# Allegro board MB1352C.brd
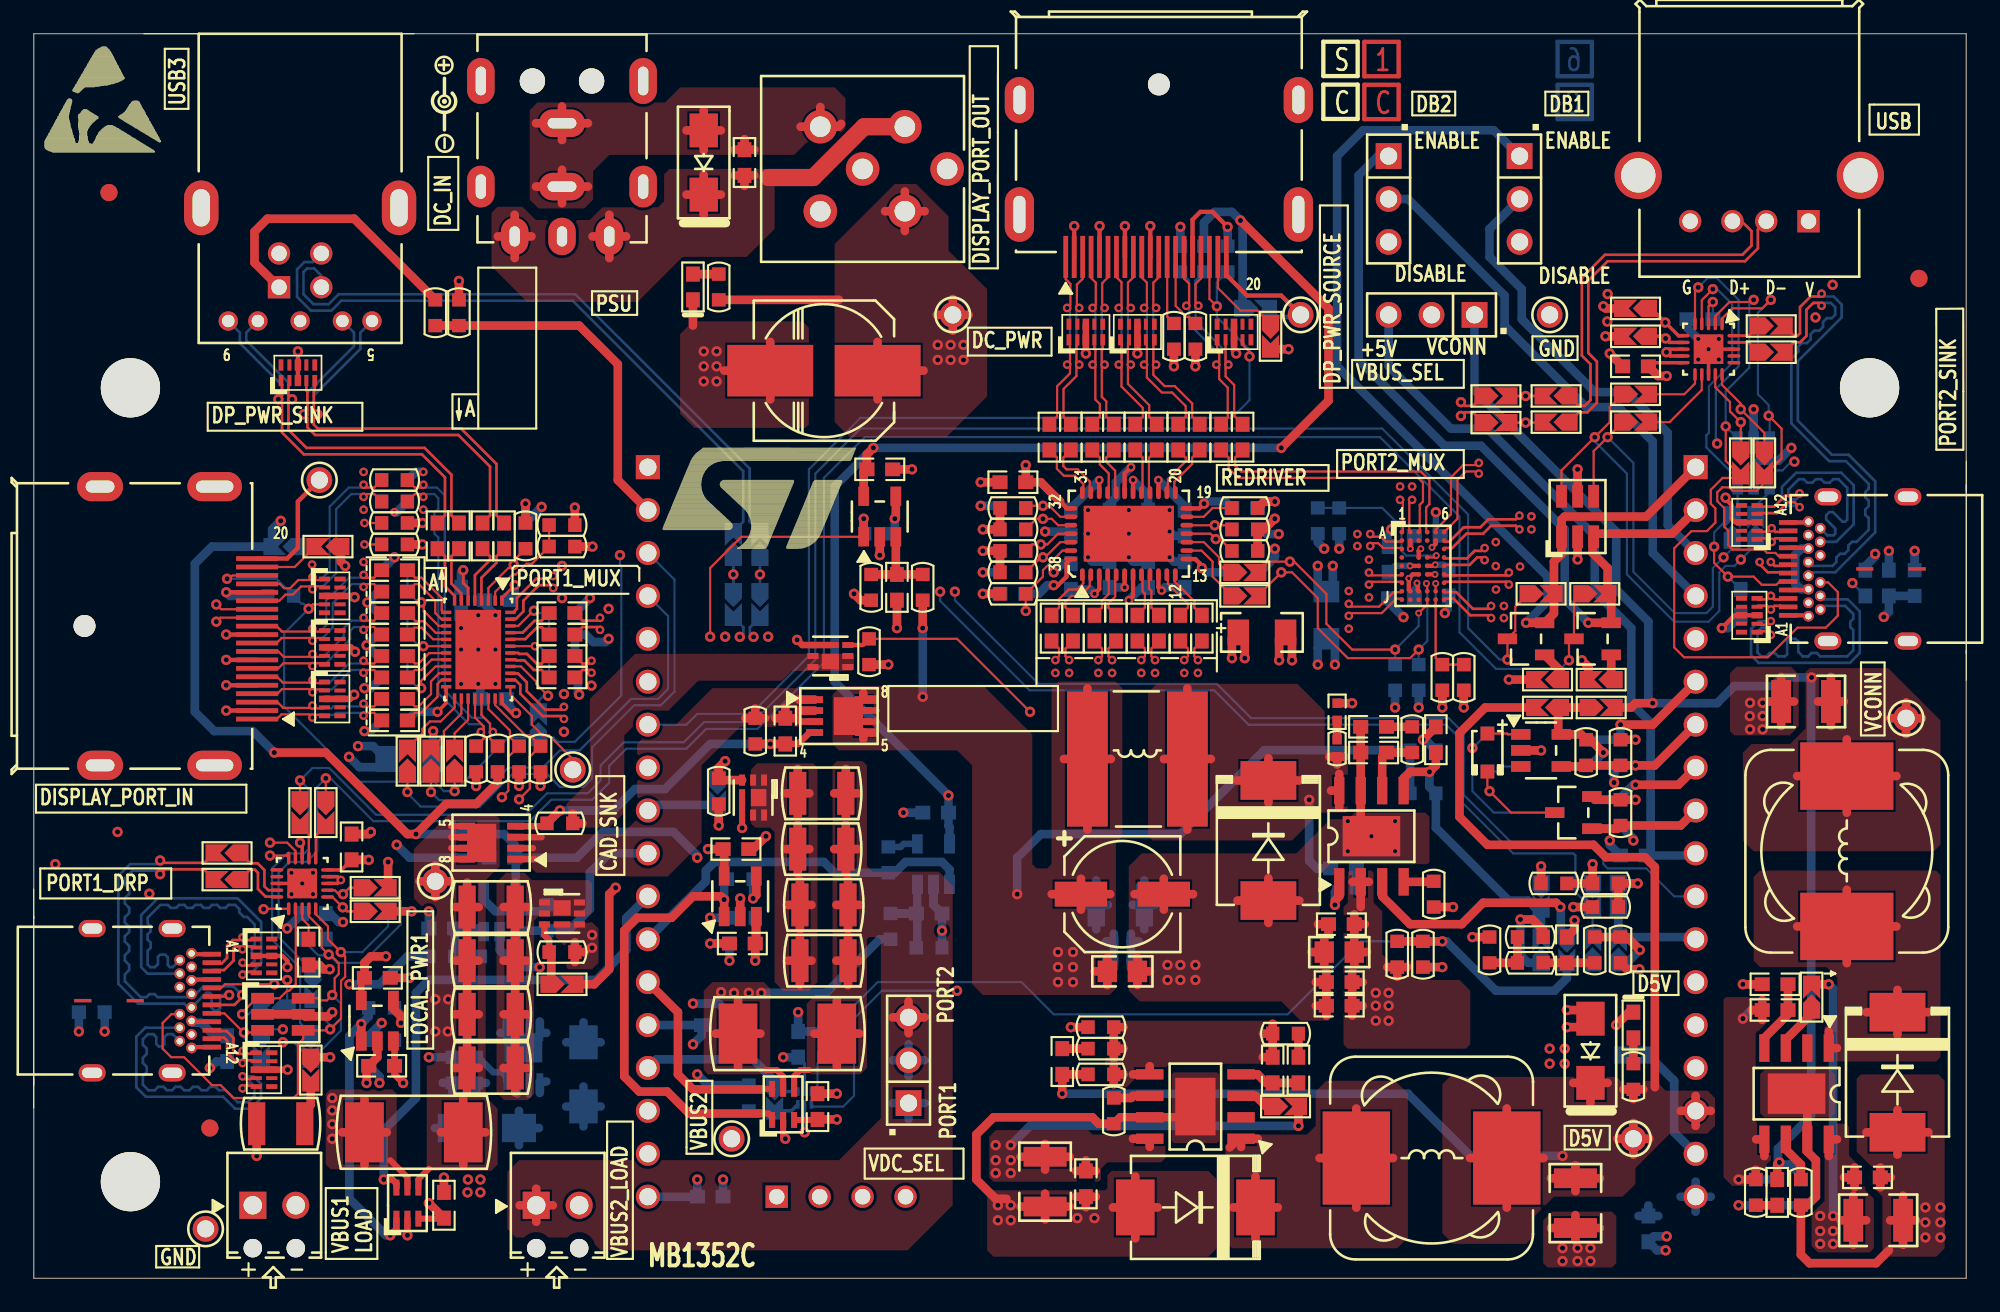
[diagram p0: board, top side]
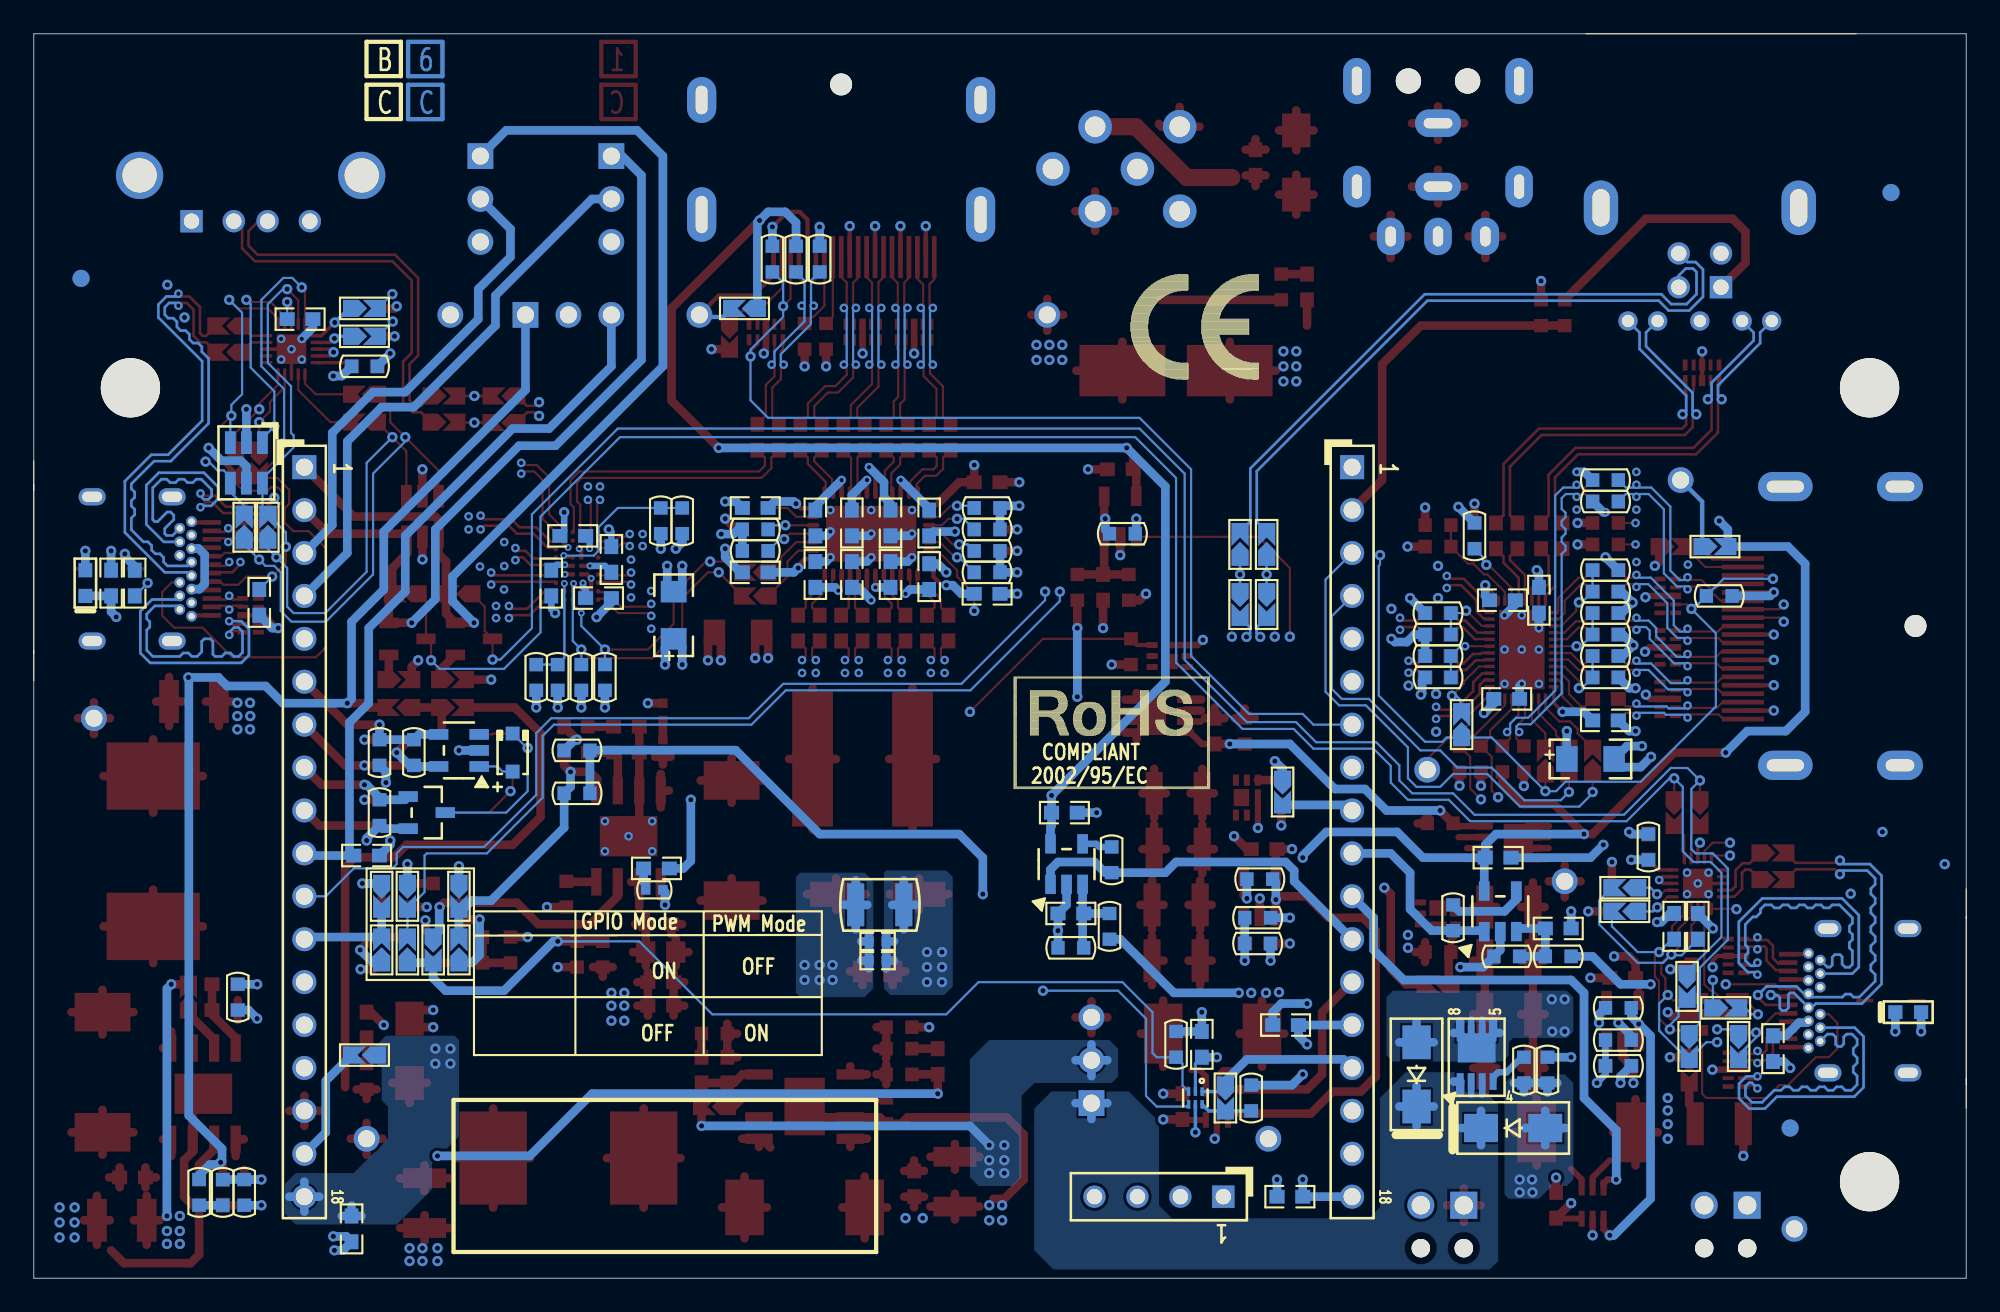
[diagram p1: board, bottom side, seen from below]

Outline 114.3 x 73.66 mm; copper layers: TOP, L2_GND, L3_SIG, L4_VCC, L5_GND, BOTTOM. Coordinates in mm from the lower left corner of the outline.
Outline path: 0,21.28 0,73.66 114.3,73.66 114.3,46.6 ; 0,21.28 0,23.05 ; 0,21.28 0,11.83 ; 0,11.83 0,10.05 ; 0,11.83 0,0 114.3,0 114.3,37.15 ; 114.3,46.6 114.3,48.38 ; 114.3,46.6 114.3,37.16 114.3,37.15 114.3,37.15 ; 114.3,37.15 114.3,35.38

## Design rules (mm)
net group AUX_P: nets AUX_N_2 AUX_P_2
net group AUX_P_1: nets AUX_N_1 AUX_P_1
net group C1_D: nets C1_D+ C1_D-
net group C1_RX1: nets C1_RX1+ C1_RX1-
net group C1_RX2: nets C1_RX2+ C1_RX2-
net group C1_TX1: nets C1_TX1+ C1_TX1-
net group C1_TX2: nets C1_TX2+ C1_TX2-
net group C2_D: nets C2_D+ C2_D-
net group C2_RX1: nets C2_RX1+ C2_RX1-
net group C2_RX2: nets C2_RX2+ C2_RX2-
net group C2_TX1: nets C2_TX1+ C2_TX1-
net group C2_TX2: nets C2_TX2+ C2_TX2-
net group CON1_D: nets CON1_D+ CON1_D-
net group CON2_D: nets CON2_D+ CON2_D-
net group DIFFPAIR18: nets NETCN1_2 NETCN1_3
net group DIFFPAIR20: nets NETC19_2 NETC20_2
net group DIFFPAIR21: nets NETC21_2 NETC22_2
net group DIFFPAIR22: nets NETC26_1 NETC37_1
net group DIFFPAIR23: nets NETC40_1 NETC43_1
net group DIFFPAIR24: nets NETC23_2 NETC24_2
net group DIFFPAIR25: nets NETC25_2 NETC36_2
net group DIFFPAIR26: nets NETC39_2 NETC42_2
net group DIFFPAIR27: nets NETC44_2 NETC46_2
net group DIFFPAIR28: nets NETC27_1 NETC28_1
net group DIFFPAIR29: nets NETC27_2 NETC28_2
net group DIFFPAIR30: nets NETC29_2 NETC30_2
net group DIFFPAIR31: nets NETC29_1 NETC30_1
net group DIFFPAIR32: nets NETC31_2 NETC32_2
net group DIFFPAIR33: nets NETC31_1 NETC32_1
net group DIFFPAIR34: nets NETC33_2 NETC34_2
net group DIFFPAIR35: nets NETC33_1 NETC34_1
net group DIFFPAIR36: nets NETC5_1 NETC6_1
net group DIFFPAIR37: nets NETC7_1 NETC8_1
net group DIFFPAIR38: nets NETC9_1 NETC10_1
net group DIFFPAIR39: nets NETC11_1 NETC12_1
net group DIFFPAIR40: nets NETC13_1 NETC14_1
net group DIFFPAIR41: nets NETR11_1 NETR12_1
net group DIFFPAIR42: nets NETCN4_2 NETCN4_3
net group DIFFPAIR43: nets NETSB70_2 NETSB71_2
net group DIFFPAIR44: nets NETSB68_2 NETSB69_2
net group L0_P: nets L0_N_2 L0_P_2
net group L0_P_1: nets L0_N_1 L0_P_1
net group L1_P: nets L1_N_2 L1_P_2
net group L1_P_1: nets L1_N_1 L1_P_1
net group L2_P: nets L2_N_2 L2_P_2
net group L2_P_1: nets L2_N_1 L2_P_1
net group L3_P: nets L3_N_2 L3_P_2
net group L3_P_1: nets L3_N_1 L3_P_1
net group SSRX: nets SSRX+ SSRX-
net group SSTX: nets SSTX+ SSTX-

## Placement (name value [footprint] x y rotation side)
C1  100nF_50V  [0603C]  42.04 66.04 90 top
C2  220uF_50V  [C310M-6]  46.74 53.72 0 top
C3  22nF  [0603C]  24.13 20.7 180 bottom
C4  220nF[N_A]  [0603C]  44.45 32.38 270 top
C5  100nF  [0603C]  60.07 49.78 90 top
C6  100nF  [0603C]  61.34 49.78 90 top
C7  100nF  [0603C]  62.61 49.78 90 top
C8  100nF  [0603C]  63.88 49.78 90 top
C9  100nF  [0603C]  65.15 49.78 90 top
C10  100nF  [0603C]  66.42 49.78 90 top
C11  100nF  [0603C]  67.69 49.78 90 top
C12  100nF  [0603C]  68.96 49.78 90 top
C13  100nF  [0603C]  70.23 49.78 90 top
C14  100nF  [0603C]  71.5 49.78 90 top
C15  1uF[N_A]  [0603C]  109.73 41.15 270 bottom
C16  1uF[N_A]  [0603C]  11.43 13.59 90 bottom
C17  100nF  [0603C]  57.91 47.12 180 top
C18  22nF  [0603C]  52.96 21.59 0 bottom
C19  100nF  [0603C]  23.88 43.94 270 top
C20  100nF  [0603C]  25.15 43.94 270 top
C21  100nF  [0603C]  26.54 43.94 270 top
C22  100nF  [0603C]  27.81 43.94 270 top
C23  100nF  [0603C]  21.34 41.91 0 top
C24  100nF  [0603C]  21.34 40.64 0 top
C25  100nF  [0603C]  21.34 39.37 0 top
C26  100nF  [0603C]  31.24 39.37 0 top
C27  100nF  [0603C]  60.2 38.48 90 top
C28  100nF  [0603C]  61.47 38.48 90 top
C29  100nF  [0603C]  62.74 38.48 90 top
C30  100nF  [0603C]  64.01 38.48 90 top
C31  100nF  [0603C]  65.28 38.48 90 top
C32  100nF  [0603C]  66.55 38.48 90 top
C33  100nF  [0603C]  67.82 38.48 90 top
C34  100nF  [0603C]  69.09 38.48 90 top
C35  10uF  [TAN-A]  72.64 38.23 180 top
C36  100nF  [0603C]  21.34 38.1 0 top
C37  100nF  [0603C]  31.24 38.1 0 top
C38  100nF  [0603C]  45.21 13.84 90 bottom
C39  100nF  [0603C]  21.34 36.83 0 top
C40  100nF  [0603C]  31.24 36.83 0 top
C41  100nF  [0603C]  50.04 47.88 0 top
C42  100nF  [0603C]  21.34 35.56 0 top
C43  100nF  [0603C]  31.24 35.56 0 top
C44  100nF  [0603C]  21.34 34.29 0 top
C45  47uF_25V  [1210C]  104.83 34.14 180 top
C46  100nF  [0603C]  21.34 33.02 0 top
C47  1uF_X5R_0603  [0603C]  94.74 53.98 0 top
C48  10nF  [0603C]  51.05 40.89 270 top
C49  750pF_50V  [0603C]  79.25 32.64 180 top
C50  11pF_50V  [0603C]  79.25 31.11 180 top
C51  1uF_X5R_0603  [0603C]  18.8 25.53 270 top
C52  22uF[GRM21BR6E226ME44]  [0805C]  64.39 18.16 0 top
C53  56uF_25V[25SVPF56M]  [CAE_6R6X6R6_H5R9]  64.39 22.73 0 top
C54  100nF  [0603C]  16.26 19.3 270 top
C55  39nF_50V  [0603C]  103 17.4 0 top
C56  100nF  [0603C]  77.47 24.26 180 bottom
C57  470nF_50V  [0603C]  90.68 19.43 90 top
C58  680pF_50V  [0603C]  103 15.88 0 top
C59  2.2uF[GRM188R61E225MA12]  [0603C]  77.34 20.95 180 top
C60  7.5nF_50V  [0603C]  60.83 12.83 90 top
C61  2.2nF_50V  [0603C]  73.28 12.32 270 top
C62  39nF_50V  [0603C]  74.8 12.32 270 top
C63  100nF  [0603C]  20.32 17.78 0 top
C64  100nF  [0603C]  41.53 25.4 0 top
C65  220nF_50V  [0603C]  108.46 5.97 0 top
C66  3.3uF_50V  [1210C]  59.82 5.71 270 top
C67  220nF_50V[N_A]  [0603C]  62.23 5.59 270 top
C68  100nF  [0603C]  24.26 4.32 90 top
C69  100nF  [0603C]  46.35 10.16 90 top
C70  33uF(TPS83360160500)  [1210C]  91.19 4.45 270 top
C71  10uF_50V  [1210C]  109.09 3.43 0 top
C72  100nF  [0603C]  20.57 12.57 180 top
C73  100nF  [0603C]  41.91 19.81 180 top
C74  8.2nF_50V  [0603C]  103.12 5.08 270 top
C75  100nF  [0603C]  71.63 45.59 0 bottom
C76  100nF  [0603C]  68.07 44.7 270 bottom
C77  100nF  [0603C]  65.91 44.7 270 bottom
C78  100nF  [0603C]  63.63 44.7 270 bottom
C79  100nF  [0603C]  61.34 44.7 270 bottom
C80  100nF  [0603C]  82.42 43.94 0 bottom
C81  100nF  [0603C]  80.14 42.55 90 bottom
C82  100nF  [0603C]  71.63 41.78 0 bottom
C83  100nF  [0603C]  68.07 41.66 90 bottom
C84  100nF  [0603C]  65.91 41.66 90 bottom
C85  100nF  [0603C]  63.63 41.66 90 bottom
C86  100nF  [0603C]  61.34 41.53 90 bottom
C87  100nF  [0603C]  83.69 41.15 270 bottom
C88  100nF  [0603C]  57.91 40.51 180 bottom
C89  100nF  [0603C]  80.9 40.26 180 bottom
C90  100nF  [0603C]  27.43 40.13 180 bottom
C91  100nF  [0603C]  25.27 40.13 270 bottom
C92  10uF  [TAN-A]  76.45 39.24 270 bottom
C93  100nF  [0603C]  27.18 34.29 180 bottom
C94  100nF  [0603C]  21.34 33.02 180 bottom
C95  10uF  [TAN-A]  22.23 30.73 0 bottom
C96  100nF  [0603C]  98.55 56.77 180 bottom
C97  100nF  [0603C]  94.61 25.02 180 bottom
C98  100nF  [0603C]  53.34 27.56 180 bottom
C99  100nF  [0603C]  27.69 24.89 180 bottom
C100  100nF  [0603C]  40.26 14.99 0 bottom
C101  100nF  [0603C]  40.01 4.83 0 bottom
C102  100nF  [0603C]  95.5 2.92 270 bottom
C103  1uF[GRM155R61E105MA12]  [0402C]  64.39 18.8 0 bottom
C104  4.7nF[GRM155R71E472KA01]  [0402C]  64.39 19.94 0 bottom
C105  22uF[GRM21BR6E226ME44]  [0805C]  77.22 19.3 180 top
C106  2.2uF[GRM188R61E225MA12]  [0603C]  77.22 16.13 180 top
C107  2.2uF[GRM188R61E225MA12]  [0603C]  77.22 17.53 180 top
C108  [N_A]  [0402C]  77.09 33.53 90 top
C109  680pF_50V  [0603C]  82.93 31.88 270 top
C110  390pF[N_A]  [0603C]  100.97 40.01 90 bottom
C111  390pF[N_A]  [0603C]  108.33 41.15 270 bottom
C112  390pF[N_A]  [0603C]  15.88 20.83 270 bottom
C113  390pF[N_A]  [0603C]  17.27 20.83 270 bottom
CN1  319AFKA06CN  [USB_A_4TH]  101.47 65.28 0 top
CN2  Display Port Source(811F20502214)  [HDMI_20SM_4HD_RA]  66.55 60.45 180 top
CN3  DC-094  [PWR_JACK_DC-094]  31.24 70.87 180 top
CN4  31930BFBA07BNHF  [USB_B_9TH_2HD_12X18R3_B]  14.5 58.66 180 top
CN5  317JD24BZTF3K3C3  [USB_C_632723300011]  105.67 41.99 90 top
CN6  Display Port Sink(811F20502214)  [HDMI_20SM_4HD_RA]  13.21 38.61 270 top
CN7  317JD24BZTF3K3C3  [USB_C_632723300011]  8.63 16.43 270 top
CN8  Header 18X1_Female  [SKT_1X18_2R54]  98.3 48.01 270 bottom
CN9  Header 18X1_Female  [SKT_1X18_2R54]  36.32 48.01 270 bottom
CN10  Header 4X1_Female  [SKT_1X4_2R54]  43.94 4.83 0 bottom
CN11  MPT 0.5_2-2.54  [PHOENIX_1725656]  12.95 4.32 0 top
CN12  MPT 0.5_2-2.54  [PHOENIX_1725656]  29.72 4.32 0 top
D1  ESDA25P35-1U1M  [D0603_21]  111.25 41.15 90 bottom
D2  ESDA25SC6[N_A]  [SOT23-6L]  101.73 48.26 0 bottom
D3  STPS2L30A[N_A]  [SMA]  32.51 12.06 90 bottom
D4  B540C-13-F  [SMC]  73.03 25.91 270 top
D5  ESDA25SC6[N_A]  [SOT23-6L]  14.73 15.62 270 top
D6  ESDA25P35-1U1M  [D0603_21]  3.43 15.75 180 bottom
D7  STPS3L40S  [SMC]  110.24 12.19 270 top
D8  STPS2L30A  [SMA]  26.8 8.89 180 bottom
D9  STPS3L40S  [SMC]  68.71 4.19 180 top
D10  ESDA5V3SC6  [SOT23-6L]  91.31 45.09 0 top
D11  BAT60JFILM  [SOD-323]  85.98 31.11 90 bottom
D12  BAT60JFILM  [SOD-323]  85.98 31.11 270 top
JP1  -  [SIP3]  80.14 66.42 270 top
JP2  -  [SIP3]  87.88 66.42 270 top
JP3  -  [SIP3]  85.22 57.02 180 top
JP5  -  [SIP3]  51.74 10.36 90 top
L1  BNX002-01  [BNX001]  49.02 65.66 0 top
L2  4.7uH(SRN8040-4R7Y)  [LSM2_SRN8040]  65.28 30.73 180 top
L4  18uH(MSS1246-183MLB)  [LSM2_12X12_H4R6]  107.24 25.27 90 top
L5  47uH(MSS1246T-473MLB)  [LSM2_12X12_H4R6]  82.68 7.11 0 top
LD1  Green  [0603D]  38.99 58.67 270 top
LD2  Green  [0603D]  94.61 14.99 90 top
NOREF  -  []  384.3 -86.36 0 top
NOREF#2  -  [unnamed#2]  10.41 8.89 0 top
NOREF#3  -  [unnamed#2]  5.71 52.7 0 top
NOREF#4  -  []  79.46 68.86 0 top
NOREF#5  -  []  141.1 158.37 0 top
NOREF#6  -  []  220.14 121.46 0 top
NOREF#7  -  []  5.71 52.7 0 top
NOREF#8  -  []  0 0 0 top
NOREF#9  -  [unnamed#2]  108.58 52.7 0 top
NOREF#10  -  []  5.71 5.71 90 top
NOREF#11  -  []  79.46 71.4 0 top
NOREF#12  -  []  0 73.66 0 top
NOREF#13  -  []  0 0 90 top
NOREF#14  -  [unnamed#2]  5.71 5.71 0 top
NOREF#15  -  [unnamed#2]  4.45 64.26 0 top
NOREF#16  -  []  -3.3 153.54 0 top
NOREF#17  -  [unnamed#2]  111.51 59.18 0 top
NOREF#18  -  []  -7.37 -7.11 0 top
NOREF#19  -  [unnamed#2]  10.41 8.89 180 bottom
NOREF#20  -  [unnamed#2]  4.45 64.26 180 bottom
NOREF#21  -  [unnamed#2]  111.51 59.18 180 bottom
R1  10K  [0603R]  23.75 57.15 270 top
R2  10K  [0603R]  25.15 57.15 90 top
R3  200K[1%]  [0603R]  80.64 19.18 270 top
R4  1M  [0603R]  67.44 55.75 270 top
R5  1M  [0603R]  68.71 55.75 270 top
R6  3K[1%]  [0603R]  82.17 19.18 90 top
R7  0  [0603R]  88.52 20.19 0 top
R8  10K  [0603R]  93.85 31.11 270 top
R9  10K  [0603R]  93.85 31.11 270 bottom
R10  1K  [0603R]  94.61 11.94 270 top
R11  0  [0603R]  21.34 45.97 180 top
R12  0  [0603R]  21.34 47.24 180 top
R13  [N_A]  [0603R]  57.91 45.59 0 top
R14  1.2K  [0603R]  71.63 45.59 0 top
R15  1M  [0603R]  21.34 44.7 180 top
R16  1K  [0603R]  31.24 44.58 0 top
R17  [N_A]  [0603R]  57.91 44.32 0 top
R18  [N_A]  [0603R]  71.63 44.32 0 top
R19  1K  [0603R]  29.08 43.94 90 top
R20  1M  [0603R]  21.34 43.43 180 top
R21  [N_A]  [0603R]  31.24 43.31 180 top
R22  [N_A]  [0603R]  57.91 43.05 0 top
R23  [N_A]  [0603R]  71.63 43.05 0 top
R24  [N_A]  [0603R]  57.91 41.78 0 top
R25  1K[N_A]  [0603R]  57.91 40.51 180 top
R26  1M[N_A]  [0603R]  21.34 45.97 0 bottom
R27  1M[N_A]  [0603R]  21.34 47.24 0 bottom
R28  1K  [0603R]  83.31 35.56 90 top
R29  [N_A]  [0603R]  84.58 35.56 270 top
R30  100K  [0603R]  67.82 60.33 90 bottom
R31  100K  [0603R]  69.22 60.33 90 bottom
R32  330  [0603R]  103.12 5.08 270 bottom
R33  10K[N_A]  [0603R]  91.82 31.11 270 bottom
R34  10K[N_A]  [0603R]  91.82 31.11 90 top
R35  10K  [0603R]  93.85 27.56 90 top
R36  100K  [0603R]  26.16 30.73 90 top
R37  100K  [0603R]  27.43 30.73 90 top
R38  2M  [0603R]  28.7 30.73 90 top
R39  2M  [0603R]  29.97 30.73 90 top
R40  51.1K  [0603R]  81.53 31.88 90 top
R41  2K  [0603R]  31.11 26.92 180 top
R42  21K  [0603R]  42.67 32.38 90 top
R43  12.4K[1%]  [0603R]  89.92 23.37 180 top
R44  9.1K[1%]  [0603R]  92.96 23.37 180 top
R45  220K[1%]  [0603R]  82.17 28.7 180 bottom
R46  20.5K[1%]  [0603R]  92.96 21.97 0 top
R47  1K_0.5W  [1210R]  27.05 15.62 0 top
R48  1K_0.5W  [1210R]  46.74 18.8 180 top
R49  1K_0.5W  [1210R]  27.05 21.97 0 top
R50  1K_0.5W  [1210R]  46.74 22.1 180 top
R51  [N_A]  [0603R]  93.85 19.43 270 top
R52  1K_0.5W  [1210R]  27.05 12.45 0 top
R53  82K[1%]  [0603R]  86.11 19.43 270 top
R54  510[1%]  [0603R]  88.52 18.67 180 top
R55  1K_0.5W  [1210R]  46.61 28.7 180 top
R56  1K_0.5W  [1210R]  27.05 18.8 0 top
R57  49.9K  [0603R]  31.24 19.3 180 top
R58  49.9K  [0603R]  40.51 28.83 90 top
R59  1K_0.5W  [1210R]  46.61 25.4 180 top
R60  [N_A]  [1210R]  64.26 22.1 180 bottom
R61  12K[1%]  [0603R]  92.33 19.43 270 top
R62  93.1K[1%]  [0603R]  82.8 22.73 90 top
R63  330K[1%]  [0603R]  50.67 20.83 270 bottom
R64  330K[1%]  [0603R]  24.13 19.05 180 bottom
R65  680  [0603R]  63.12 14.86 0 top
R66  22K  [0603R]  74.04 14.48 0 top
R67  100  [0603R]  63.12 13.59 180 top
R68  4.99K  [0603R]  63.12 12.06 180 top
R69  0.005[1%]  [2512R]  22.48 8.64 180 top
R70  0.005[1%]  [2512R]  44.58 14.48 180 top
R71  162K  [0603R]  63.88 9.91 90 top
R72  21K  [0603R]  26.16 12.32 90 bottom
R73  21K  [0603R]  24.77 12.32 270 bottom
R74  100  [0603R]  101.85 5.08 270 top
R75  4.99K  [0603R]  104.52 5.08 90 bottom
R76  187K  [0603R]  104.52 5.08 90 top
R77  49.9K[1%]  [0603R]  20.57 14.1 180 bottom
R78  49.9K[1%]  [0603R]  41.91 21.34 180 bottom
R79  49.9K[1%]  [0603R]  20.57 12.57 0 bottom
R80  49.9K[1%]  [0603R]  41.91 19.81 0 bottom
R81  1M  [0603R]  70.61 60.33 90 bottom
R82  [N_A]  [0603R]  46.74 13.84 270 bottom
R83  330K[1%]  [0603R]  52.58 40.89 270 top
R84  49.9K[1%]  [0603R]  49.53 40.89 90 top
R85  1K  [0603R]  57.91 45.59 180 bottom
R86  1K  [0603R]  77.22 44.83 270 bottom
R87  [N_A]  [0603R]  75.95 44.83 90 bottom
R88  1K  [0603R]  71.63 44.32 180 bottom
R89  1K  [0603R]  57.91 44.32 180 bottom
R90  [N_A]  [0603R]  29.08 43.94 270 bottom
R91  1K  [0603R]  71.63 43.05 180 bottom
R92  1K  [0603R]  57.91 43.05 180 bottom
R93  [N_A]  [0603R]  21.34 41.91 0 bottom
R94  [N_A]  [0603R]  57.91 41.78 180 bottom
R95  1K  [0603R]  21.34 40.64 180 bottom
R96  1M  [0603R]  14.61 40.39 180 bottom
R97  [N_A]  [0603R]  31.24 39.37 180 bottom
R98  1K  [0603R]  21.34 39.37 180 bottom
R99  1K  [0603R]  31.24 38.1 0 bottom
R100  [N_A]  [0603R]  21.34 38.1 0 bottom
R101  43K  [0603R]  49.91 44.07 0 bottom
R102  1K  [0603R]  31.24 36.83 0 bottom
R103  1K  [0603R]  21.34 36.83 0 bottom
R104  1K  [0603R]  84.58 35.56 270 bottom
R105  [N_A]  [0603R]  83.31 35.56 90 bottom
R106  10K  [0603R]  81.92 35.56 270 bottom
R107  10K  [0603R]  80.52 35.56 270 bottom
R108  [N_A]  [0603R]  31.24 35.56 180 bottom
R109  [N_A]  [0603R]  21.34 35.56 180 bottom
R110  0  [0402R]  77.6 22.99 180 bottom
R111  [N_A]  [0402R]  77.09 31.37 270 top
R112  100K  [0603R]  94.74 53.98 180 bottom
R113  10K  [0603R]  93.85 27.56 270 bottom
R114  100K  [0603R]  18.8 25.53 90 bottom
R115  43K  [0603R]  50.55 24.77 90 bottom
R116  43K  [0603R]  30.35 21.34 90 bottom
R117  1.2K  [0603R]  102.23 16.64 90 bottom
R118  49.9K[1%]  [0603R]  52.96 19.56 180 bottom
R119  49.9K[1%]  [0603R]  27.18 19.05 180 bottom
R120  15K[1%]  [0603R]  42.29 10.67 90 bottom
R121  24.9K  [0603R]  41.78 23.62 0 bottom
R122  24.9K  [0603R]  20.57 16 0 bottom
R123  680  [0603R]  101.85 5.08 90 bottom
R124  10K  [0603R]  49.4 37.08 90 top
R125  3K  [0603R]  40.51 58.67 270 top
R126  1K_0.5W  [1210R]  14.61 9.14 180 top
R127  0  [0603R]  82.17 31.24 180 bottom
SB1  Solder Bridge ON  [SB_0603]  73.15 55.75 90 top
SB2  Solder Bridge OFF  [SB_0603]  93.73 19.43 270 bottom
SB3  Solder Bridge OFF  [SB_0603]  89.15 19.43 270 bottom
SB4  Solder Bridge OFF  [SB_0603]  89.15 40.51 180 top
SB5  Solder Bridge OFF  [SB_0603]  92.33 40.51 180 top
SB6  Solder Bridge ON  [SB_0603]  17.4 43.31 0 top
SB7  Solder Bridge ON  [SB_0603]  71.63 41.78 180 top
SB8  Solder Bridge OFF  [SB_0603]  89.53 33.78 0 top
SB9  Solder Bridge ON  [SB_0603]  92.71 33.78 180 top
SB10  Solder Bridge ON  [SB_0603]  71.63 40.39 180 top
SB11  Solder Bridge ON  [SB_0603]  92.71 35.43 0 top
SB12  Solder Bridge ON  [SB_0603]  89.53 35.43 0 top
SB13  Solder Bridge ON  [SB_0603]  89.15 22.61 90 bottom
SB14  Solder Bridge ON  [SB_0603]  93.73 22.61 90 bottom
SB15  Solder Bridge ON  [SB_0603]  92.2 22.61 90 bottom
SB16  Solder Bridge OFF  [SB_0603]  94.74 55.75 0 top
SB17  Solder Bridge OFF  [SB_0603]  94.74 57.4 0 top
SB18  Solder Bridge ON  [SB_0603]  22.1 30.61 270 top
SB19  Solder Bridge ON  [SB_0603]  23.5 30.61 270 top
SB20  Solder Bridge ON  [SB_0603]  24.89 30.61 270 top
SB21  Solder Bridge ON  [SB_0603]  15.75 27.56 90 top
SB22  Solder Bridge ON  [SB_0603]  17.27 27.56 90 top
SB23  Solder Bridge OFF  [SB_0603]  92.2 19.43 270 bottom
SB24  Solder Bridge OFF  [SB_0603]  43.81 10.67 90 bottom
SB25  Solder Bridge OFF  [SB_0603]  16.38 12.32 90 top
SB26  Solder Bridge OFF  [SB_0603]  90.68 19.43 90 bottom
SB27  Solder Bridge OFF  [SB_0603]  20.19 21.72 180 top
SB28  Solder Bridge OFF  [SB_0603]  20.19 23.11 180 top
SB33  Solder Bridge ON  [SB_0603]  105.16 16.64 270 top
SB35  Solder Bridge ON  [SB_0603]  31.24 17.4 180 top
SB36  Solder Bridge ON  [SB_0603]  40.44 28.78 90 bottom
SB37  Solder Bridge ON  [SB_0603]  74.04 10.16 180 top
SB40  Solder Bridge ON  [SB_0603]  72.26 57.4 180 bottom
SB41  Solder Bridge OFF  [SB_0603]  102.36 48.26 90 top
SB42  Solder Bridge OFF  [SB_0603]  100.97 48.26 90 top
SB43  Solder Bridge ON  [SB_0603]  14.86 43.31 0 bottom
SB44  Solder Bridge OFF  [SB_0603]  100.46 44.45 270 bottom
SB45  Solder Bridge OFF  [SB_0603]  101.85 44.45 270 bottom
SB48  Solder Bridge OFF  [SB_0603]  29.84 32.77 270 bottom
SB49  Solder Bridge ON  [SB_0603]  94.74 57.4 0 bottom
SB50  Solder Bridge ON  [SB_0603]  94.74 55.75 0 bottom
SB51  Solder Bridge ON  [SB_0603]  94.74 52.32 180 top
SB52  Solder Bridge ON  [SB_0603]  94.74 50.67 180 top
SB53  Solder Bridge OFF  [SB_0603]  14.22 16 0 bottom
SB54  Solder Bridge ON  [SB_0603]  20.19 23.11 180 bottom
SB55  Solder Bridge ON  [SB_0603]  20.19 21.72 180 bottom
SB56  Solder Bridge OFF  [SB_0603]  16.38 13.72 90 bottom
SB57  Solder Bridge OFF  [SB_0603]  16.51 17.27 90 bottom
SB58  Solder Bridge OFF  [SB_0603]  13.46 13.72 90 bottom
SB59  Solder Bridge ON  [SB_0603]  94.74 13.21 180 bottom
SB60  Solder Bridge OFF  [SB_0603]  42.95 39.88 90 bottom
SB61  Solder Bridge OFF  [SB_0603]  41.38 39.88 90 bottom
SB62  Solder Bridge ON  [SB_0603]  42.95 43.43 270 bottom
SB63  Solder Bridge ON  [SB_0603]  41.38 43.43 270 bottom
SB64  Solder Bridge ON  [SB_0603]  90.04 50.67 0 top
SB65  Solder Bridge ON  [SB_0603]  90.04 52.22 0 top
SB66  Solder Bridge OFF  [SB_0603]  86.49 50.65 180 top
SB67  Solder Bridge OFF  [SB_0603]  86.49 52.22 180 top
SB68  Solder Bridge ON  [SB_0603]  102.77 56.36 180 top
SB69  Solder Bridge ON  [SB_0603]  102.77 54.81 180 top
SB70  Solder Bridge ON  [SB_0603]  11.43 23.6 0 top
SB71  Solder Bridge ON  [SB_0603]  11.43 25.17 0 top
T2  FDV303N  [SOT-23]  88.27 37.85 0 top
T3  FDV303N  [SOT-23]  92.2 37.85 0 top
T4  FDV303N  [SOT-23]  91.06 27.56 0 top
T5  STL6N2VH5  [DFN6_0R65_2X2_2TP_C]  47.12 36.83 90 top
T6  STL9P3LLH6  [SOIC8_MOS_S]  27.05 25.78 90 top
T7  STL9P3LLH6  [SOIC8_MOS_S]  47.62 33.27 270 top
T8  STL6N2VH5  [DFN6_0R65_2X2_2TP_C]  31.24 21.59 270 top
T9  STL6N2VH5  [DFN6_0R65_2X2_2TP_C]  42.55 28.45 180 top
T10  STL9P3LLH6  [SOIC8_MOS_S]  28.96 13.08 180 bottom
T12  FDV303N  [SOT-23]  91.06 27.56 0 bottom
TP1  DP_PWR_SOURCE  [TP]  74.93 57.02 180 top
TP2  PSU  [TP]  54.36 57.02 270 top
TP3  Ground  [TP]  89.66 57.02 0 top
TP4  DP_PWR_SINK  [TP]  16.89 47.24 270 top
TP5  VCONN  [TP]  110.74 33.15 90 top
TP6  CAD_SNK  [TP]  31.88 30.1 0 top
TP7  D5V  [TP]  94.61 8.26 90 top
TP8  Ground  [TP]  10.16 2.92 0 top
TP9  LOCAL_PWR1  [TP]  23.75 23.5 0 top
TP10  VBUS2  [TP]  41.27 8.26 0 top
U1  HSP051-4M10  [DFN10_0R5_2R5X1]  62.23 56.01 0 top
U2  HSP051-4M10  [DFN10_0R5_2R5X1]  65.28 56.01 0 top
U3  HSP051-4M10  [DFN10_0R5_2R5X1]  70.99 56.01 0 top
U4  HSP051-4M10  [DFN10_0R5_2R5X1]  15.62 53.59 0 top
U5  HSP051-4M10  [DFN10_0R5_2R5X1]  101.47 44.74 90 top
U6  SN65DP141RLJ  [QFN38_0R5_5X7]  64.77 44.07 90 top
U7  STG5123  [DFN6_0R4_1R2X1]  45.59 10.67 0 bottom
U8  CBTL08GP053EVY  [FBGA40_0R5_3R25X4R75]  82.17 42.16 0 top
U9  HSP051-4M10  [DFN10_0R5_2R5X1]  17.65 40.39 270 top
U10  STMPS2161STR  [SOT23-5]  89.15 31.24 90 bottom
U11  HSP051-4M10  [DFN10_0R5_2R5X1]  101.47 39.24 90 top
U12  HSP051-4M10  [DFN10_0R5_2R5X1]  17.65 37.34 270 top
U13  TUSB546-DCI  [QFN40_0R4_6X4]  26.29 37.21 270 top
U14  STMPS2161STR  [SOT23-5]  89.15 31.24 270 top
U15  HSP051-4M10  [DFN10_0R5_2R5X1]  17.65 34.29 270 top
U16  TPD8S300RUKR  [QFN20_0R4_3X3_TP1R75]  99.06 54.99 270 top
U17  TPD8S300RUKR  [QFN20_0R4_3X3_TP1R75]  15.88 23.37 90 top
U18  TPS54540  [SOIC8_1R27_4R9X6_TP]  79.12 26.16 0 top
U19  HSP051-4M10  [DFN10_0R5_2R5X1]  13.61 19.08 270 top
U20  HSP051-4M10  [DFN10_0R5_2R5X1]  13.61 12.34 270 top
U21  L7985A  [SOIC8_1R27_4R9X6_TP]  104.27 10.92 180 top
U22  L7985A  [SOIC8_1R27_4R9X6_TP]  68.71 10.16 90 top
U23  INA199A1DCKR  [SC70-6]  22.1 4.45 0 top
U24  INA199A1DCKR  [SC70-6]  44.32 10.29 0 top
U25  TSV911ILT  [SOT23-5]  20.32 15.24 0 top
U26  TSV911ILT  [SOT23-5]  41.78 22.61 0 top
U27  TSV911ILT  [SOT23-5]  53.21 24.51 180 bottom
U28  TSV911ILT  [SOT23-5]  27.56 21.72 180 bottom
U29  TSV911ILT  [SOT23-5]  50.04 45.09 0 top
Z1  SMAJ20A-TR  [SMA]  39.62 66.04 90 top
Z2  SMAJ5.0A-TR  [SMA]  92.08 13.46 90 top

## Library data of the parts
C1 C3-C34 C36-C44 C46-C51 C54-C65 C67-C69 C72-C91 C93 C94 C96-C102 C106 C107 C109-C113 = 0603C
C2 = C310M-6
C35 C92 C95 = TAN-A
C45 C66 C70 C71 = 1210C
C52 C105 = 0805C
C53 = CAE_6R6X6R6_H5R9
C103 C104 C108 = 0402C
CN1 = USB_A_4TH
CN2 CN6 = HDMI_20SM_4HD_RA
CN3 = PWR_JACK_DC-094
CN4 = USB_B_9TH_2HD_12X18R3_B
CN5 CN7 = USB_C_632723300011
CN8 CN9 = SKT_1X18_2R54
CN10 = SKT_1X4_2R54
CN11 CN12 = PHOENIX_1725656
D1 D6 = D0603_21
D2 D5 D10 = SOT23-6L
D3 D8 Z1 Z2 = SMA
D4 D7 D9 = SMC
D11 D12 = SOD-323
JP1-JP3 JP5 = SIP3
L1 = BNX001
L2 = LSM2_SRN8040
L4 L5 = LSM2_12X12_H4R6
LD1 LD2 = 0603D
R1-R46 R51 R53 R54 R57 R58 R61-R68 R71-R109 R112-R125 R127 = 0603R
R47-R50 R52 R55 R56 R59 R60 R126 = 1210R
R69 R70 = 2512R
R110 R111 = 0402R
SB1-SB28 SB33 SB35-SB37 SB40-SB45 SB48-SB71 = SB_0603
T2-T4 T12 = SOT-23
T5 T8 T9 = DFN6_0R65_2X2_2TP_C
T6 T7 T10 = SOIC8_MOS_S
TP1-TP10 = TP
U1-U5 U9 U11 U12 U15 U19 U20 = DFN10_0R5_2R5X1
U6 = QFN38_0R5_5X7
U7 = DFN6_0R4_1R2X1
U8 = FBGA40_0R5_3R25X4R75
U10 U14 U25-U29 = SOT23-5
U13 = QFN40_0R4_6X4
U16 U17 = QFN20_0R4_3X3_TP1R75
U18 U21 U22 = SOIC8_1R27_4R9X6_TP
U23 U24 = SC70-6

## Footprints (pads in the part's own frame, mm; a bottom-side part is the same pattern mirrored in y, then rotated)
0402C
  rect 0.559x0.559 smd: 1(-0.508,0) 2(0.508,0)
0402R
  rect 0.559x0.559 smd: 1(-0.508,0) 2(0.508,0)
0603C
  rect 0.889x0.813 smd: 1(-0.762,0) 2(0.762,0)
0603D
  rect 0.889x0.813 smd: 1(-0.762,0) 2(0.762,0)
0603R
  rect 0.787x0.813 smd: 1(-0.762,0) 2(0.762,0)
0805C
  rect 1.143x1.27 smd: 1(-0.889,0) 2(0.889,0)
1210C
  rect 1.168x2.54 smd: 1(-1.473,0) 2(1.473,0)
1210R
  rect 1.016x2.54 smd: 1(-1.422,0) 2(1.422,0)
2512R
  rect 2.286x3.556 smd: 1(-2.921,0) 2(2.921,0)
BNX001
  round 1.981 hole 1.219: 1(2.5,2.5) 2(-2.5,2.5) 3(2.5,-2.5) 4(0,0) 5(5,0) 6(-2.5,-2.5)
C310M-6
  rect 5.08x3.048 smd: 1(3.175,0) 2(-3.175,0)
CAE_6R6X6R6_H5R9
  rect 3.099x1.473 smd: 1(-2.45,0) 2(2.45,0)
D0603_21
  rect 0.838x0.813 smd: 1(-0.762,0) 2(0.762,0)
DFN6_0R4_1R2X1
  rect 0.203x0.508 smd: 1(-0.4,-0.379) 2(0,-0.379) 3(0.4,-0.379) 4(0.4,0.379) 5(0,0.379) 6(-0.4,0.379)
DFN6_0R65_2X2_2TP_C
  rect 0.356x0.66 smd: 1(-0.65,-1.035) 2(0,-1.035) 3(0.65,-1.035) 4(0.65,1.035) 5(0,1.035) 6(-0.65,1.035)
  rect 0.914x1.016 smd: 7(-0.325,0)
  rect 0.356x0.991 smd: 8(0.65,0)
DFN10_0R5_2R5X1
  rect 0.279x0.66 smd: 1(-1,-0.46) 5(1,-0.46) 6(1,0.46) 10(-1,0.46)
  rect 0.229x0.66 smd: 2(-0.5,-0.46) 4(0.5,-0.46) 7(0.5,0.46) 9(-0.5,0.46)
  rect 0.381x0.66 smd: 3(0,-0.46) 8(0,0.46)
FBGA40_0R5_3R25X4R75
  round 0.279 smd: A1(-1.25,2) A2(-0.75,2) A3(-0.25,2) A4(0.25,2) A5(0.75,2) A6(1.25,2) B1(-1.25,1.5) B2(-0.75,1.5) B3(-0.25,1.5) B4(0.25,1.5) B5(0.75,1.5) B6(1.25,1.5) C1(-1.25,1) C6(1.25,1) D1(-1.25,0.5) D3(-0.25,0.5) D4(0.25,0.5) D6(1.25,0.5) E1(-1.25,0) E3(-0.25,0) E4(0.25,0) E6(1.25,0) F1(-1.25,-0.5) F3(-0.25,-0.5) F4(0.25,-0.5) F6(1.25,-0.5) G1(-1.25,-1) G6(1.25,-1) H1(-1.25,-1.5) H2(-0.75,-1.5) H3(-0.25,-1.5) H4(0.25,-1.5) H5(0.75,-1.5) H6(1.25,-1.5) J1(-1.25,-2) J2(-0.75,-2) J3(-0.25,-2) J4(0.25,-2) J5(0.75,-2) J6(1.25,-2)
HDMI_20SM_4HD_RA
  round 1.295 hole 1.295: (0,-10.21)
  rect 0.279x2.489 smd: 1(5.51,0) 2(5.01,0) 3(4.51,0) 4(4.01,0) 5(3.51,0) 6(3.01,0) 7(2.51,0) 8(2.01,0) 9(1.51,0) 10(1.01,0) 11(0.51,0) 12(0.01,0) 13(-0.49,0) 14(-0.99,0) 15(-1.49,0) 16(-1.99,0) 17(-2.49,0) 18(-2.99,0) 19(-3.49,0) 20(-3.99,0)
  oval 1.727x3.226 hole 0.711x2.21: 21(8.25,-2.51) 22(-8.25,-2.51)
  oval 1.727x2.718 hole 0.711x1.702: 23(8.25,-9.29) 24(-8.25,-9.29)
LSM2_12X12_H4R6
  rect 3.988x5.512 smd: 1(-4.45,0) 2(4.45,0)
LSM2_SRN8040
  rect 2.413x8.001 smd: 1(-2.957,0) 2(2.957,0)
PHOENIX_1725656
  round 1.092 hole 1.092 unplated: (0,-2.54) (2.54,-2.54)
  rect 1.6x1.6 hole 1.092: 1(0,0)
  round 1.6 hole 1.092: 2(2.54,0)
PWR_JACK_DC-094
  round 1.499 hole 1.499 unplated: (-1.75,0) (1.75,0)
  oval 2.718x1.626 hole 1.702x0.61: 1(0,6.25) 3(0,2.5)
  oval 1.626x2.21 hole 0.61x1.194: 2(-2.8,9.2) 4(0,9.2) 5(2.8,9.2)
  oval 1.626x2.464 hole 0.61x1.448: 6(-4.8,6.25) 7(4.8,6.25)
  oval 1.626x2.718 hole 0.61x1.702: 8(4.8,0) 9(-4.8,0)
QFN20_0R4_3X3_TP1R75
  oval 0.762x0.203 smd: 1(-1.5,0.8) 2(-1.5,0.4) 3(-1.5,0) 4(-1.5,-0.4) 5(-1.5,-0.8) 11(1.5,-0.8) 12(1.5,-0.4) 13(1.5,0) 14(1.5,0.4) 15(1.5,0.8)
  oval 0.203x0.762 smd: 6(-0.8,-1.5) 7(-0.4,-1.5) 8(0,-1.5) 9(0.4,-1.5) 10(0.8,-1.5) 16(0.8,1.5) 17(0.4,1.5) 18(0,1.5) 19(-0.4,1.5) 20(-0.8,1.5)
  rect 1.753x1.753 smd: 21(0,0)
QFN38_0R5_5X7
  oval 0.762x0.279 smd: 1(-2.431,2.75) 2(-2.431,2.25) 3(-2.431,1.75) 4(-2.431,1.25) 5(-2.431,0.75) 6(-2.431,0.25) 7(-2.431,-0.25) 8(-2.431,-0.75) 9(-2.431,-1.25) 10(-2.431,-1.75) 11(-2.431,-2.25) 12(-2.431,-2.75) 20(2.431,-2.75) 21(2.431,-2.25) 22(2.431,-1.75) 23(2.431,-1.25) 24(2.431,-0.75) 25(2.431,-0.25) 26(2.431,0.25) 27(2.431,0.75) 28(2.431,1.25) 29(2.431,1.75) 30(2.431,2.25) 31(2.431,2.75)
  oval 0.279x0.762 smd: 13(-1.5,-3.435) 14(-1,-3.435) 15(-0.5,-3.435) 16(0,-3.435) 17(0.5,-3.435) 18(1,-3.435) 19(1.5,-3.435) 32(1.5,3.435) 33(1,3.435) 34(0.5,3.435) 35(0,3.435) 36(-0.5,3.435) 37(-1,3.435) 38(-1.5,3.435)
  rect 3.302x5.334 smd: 39(0,0)
QFN40_0R4_6X4
  rect 0.61x0.203 smd: 1(-2.9,1.4) 2(-2.9,1) 3(-2.9,0.6) 4(-2.9,0.2) 5(-2.9,-0.2) 6(-2.9,-0.6) 7(-2.9,-1) 8(-2.9,-1.4) 21(2.9,-1.4) 22(2.9,-1) 23(2.9,-0.6) 24(2.9,-0.2) 25(2.9,0.2) 26(2.9,0.6) 27(2.9,1) 28(2.9,1.4)
  rect 0.203x0.61 smd: 9(-2.2,-1.9) 10(-1.8,-1.9) 11(-1.4,-1.9) 12(-1,-1.9) 13(-0.6,-1.9) 14(-0.2,-1.9) 15(0.2,-1.9) 16(0.6,-1.9) 17(1,-1.9) 18(1.4,-1.9) 19(1.8,-1.9) 20(2.2,-1.9) 29(2.2,1.9) 30(1.8,1.9) 31(1.4,1.9) 32(1,1.9) 33(0.6,1.9) 34(0.2,1.9) 35(-0.2,1.9) 36(-0.6,1.9) 37(-1,1.9) 38(-1.4,1.9) 39(-1.8,1.9) 40(-2.2,1.9)
  rect 4.699x2.692 smd: 41(0,0)
SB_0603
  round 0.152 smd: 1(-0.762,0) 2(0.762,0)
SC70-6
  rect 0.356x0.94 smd: 1(-0.65,-0.92) 2(0,-0.92) 3(0.65,-0.92) 4(0.65,0.92) 5(0,0.92) 6(-0.65,0.92)
SIP3
  rect 1.524x1.524 hole 1.016: 1(0,0)
  round 1.524 hole 1.016: 2(2.54,0) 3(5.08,0)
SKT_1X4_2R54
  rect 1.321x1.321 hole 0.914: 1(0,0)
  round 1.321 hole 0.914: 2(2.54,0) 3(5.08,0) 4(7.62,0)
SKT_1X18_2R54
  rect 1.422x1.422 hole 1.016: 1(0,0)
  round 1.422 hole 1.016: 2(2.54,0) 3(5.08,0) 4(7.62,0) 5(10.16,0) 6(12.7,0) 7(15.24,0) 8(17.78,0) 9(20.32,0) 10(22.86,0) 11(25.4,0) 12(27.94,0) 13(30.48,0) 14(33.02,0) 15(35.56,0) 16(38.1,0) 17(40.64,0) 18(43.18,0)
SMA
  rect 2.007x1.676 smd: 1(1.9,0) 2(-1.9,0)
SMC
  rect 2.286x3.302 smd: 1(3.555,0) 2(-3.555,0)
SOD-323
  rect 0.813x0.813 smd: 1(-1.125,0) 2(1.125,0)
SOIC8_1R27_4R9X6_TP
  rect 0.61x1.626 smd: 1(-1.905,-2.7) 2(-0.635,-2.7) 3(0.635,-2.7) 4(1.905,-2.7) 5(1.905,2.7) 6(0.635,2.7) 7(-0.635,2.7) 8(-1.905,2.7)
  rect 3.404x2.388 smd: 9(0,0)
SOIC8_MOS_S
  rect 0.406x0.991 smd: 1(-0.975,-1.44) 2(-0.325,-1.44) 3(0.325,-1.44) 4(0.975,-1.44) 5(0.975,1.44) 6(0.325,1.44) 7(-0.325,1.44) 8(-0.975,1.44)
SOT23-5
  rect 0.635x1.143 smd: 1(-0.95,-1.2) 2(0,-1.2) 3(0.95,-1.2) 4(0.95,1.2) 5(-0.95,1.2)
SOT23-6L
  rect 0.635x1.346 smd: 1(-0.95,-1.2) 2(0,-1.2) 3(0.95,-1.2) 4(0.95,1.2) 5(0,1.2) 6(-0.95,1.2)
SOT-23
  rect 1.143x0.635 smd: 1(1.1,-0.95) 2(1.1,0.95) 3(-1.1,0)
TAN-A
  rect 1.27x1.524 smd: 1(1.397,0) 2(-1.397,0)
TP
  round 1.524 hole 1.016: 1(0,0)
unnamed#2
  round 1.016 smd: (0,0)
USB_A_4TH
  rect 1.321x1.321 hole 0.914: 1(3.5,-2.71)
  round 1.321 hole 0.914: 2(1,-2.71) 3(-1,-2.71) 4(-3.5,-2.71)
  round 2.794 hole 2.032: 5(-6.57,0) 6(6.57,0)
USB_B_9TH_2HD_12X18R3_B
  rect 1.321x1.321 hole 0.914: 1(0,0)
  round 1.321 hole 0.914: 2(-2.5,0) 3(-2.5,-2) 4(0,-2)
  round 1.143 hole 0.737: 5(-5.5,2) 6(-3.75,2) 7(-1.25,2) 8(1.25,2) 9(3,2)
  oval 2.032x3.226 hole 1.016x2.21: 10(-7.1,-4.7) 11(4.6,-4.7)
USB_C_632723300011
  oval 1.016x1.6 hole 0.61x1.194: 1(-4.27,-0.45) 2(4.27,-0.45) 3(-4.27,-5.18) 4(4.27,-5.18)
  rect 0.203x1.016 smd: 5(0,-2.63) 6(0,-5.73)
  rect 0.279x1.092 smd: A1(-2.75,1.9) A2(-2.25,1.9) A3(-1.75,1.9) A4(-1.25,1.9) A5(-0.75,1.9) A6(-0.25,1.9) A7(0.25,1.9) A8(0.75,1.9) A9(1.25,1.9) A10(1.75,1.9) A11(2.25,1.9) A12(2.75,1.9)
  round 0.635 hole 0.381: B1(2.8,0.7) B2(2.4,0) B3(1.6,0) B4(1.2,0.7) B5(0.8,0) B6(0.4,0.7) B7(-0.4,0.7) B8(-0.8,0) B9(-1.2,0.7) B10(-1.6,0) B11(-2.4,0) B12(-2.8,0.7) B13(2,0.7) B14(-2,0.7)

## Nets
+3V3: C38.1 C41.1 C63.1 C64.1 C68.1 C69.1 C98.1 C99.1 C100.1 CN9.14 R26.2 R31.2 R37.1 R77.2 R78.2 R120.2 SB40.2 SB43.1 U7.2 U23.3 U24.3 U25.5 U26.5 U27.5 U28.5 U29.5
+5V: C97.1 CN8.10 JP3.3
D5V: C60.1 C70.1 CN8.16 L5.2 R10.2 R68.2 SB8.1 TP7.1 Z2.2
GND: C2.2 C3.2 C15.1 C16.1 C17.2 C18.2 C35.2 C38.2 C41.2 C45.2 C47.1 C48.2 C49.2 C50.2 C51.1 C52.2 C53.2 C54.2 C57.2 C59.2 C63.2 C64.2 C65.2 C66.2 C67.2 C68.2 C69.2 C70.2 C71.2 C72.2 C73.2 C75.2 C76.2 C77.2 C78.2 C79.2 C80.2 C81.2 C82.2 C83.2 C84.2 C85.2 C86.2 C87.2 C88.2 C89.2 C90.2 C91.2 C92.2 C93.2 C94.2 C95.2 C96.2 C97.2 C98.2 C99.2 C100.2 C101.2 C102.2 C103.2 C104.2 C105.2 C106.2 C107.2 C108.2 C110.1 C111.1 C112.1 C113.1 CN1.4 CN1.5 CN1.6 CN2.2 CN2.5 CN2.8 CN2.11 CN2.16 CN2.21 CN2.22 CN2.23 CN2.24 CN4.4 CN4.7 CN4.10 CN4.11 CN5.1 CN5.2 CN5.3 CN5.4 CN5.A1 CN5.A12 CN5.B1 CN5.B12 CN5.B13 CN5.B14 CN6.2 CN6.5 CN6.8 CN6.11 CN6.16 CN6.21 CN6.22 CN6.23 CN6.24 CN7.1 CN7.2 CN7.3 CN7.4 CN7.A1 CN7.A12 CN7.B1 CN7.B12 CN7.B13 CN7.B14 CN8.5 CN9.5 CN11.2 CN12.2 D1.2 D2.2 D2.5 D4.1 D5.2 D5.5 D6.2 D7.1 D9.1 D10.2 D10.5 JP1.3 JP2.3 L1.4 L1.5 L1.6 LD1.2 LD2.2 R2.2 R4.2 R5.2 R6.1 R14.2 R15.1 R16.2 R18.2 R19.2 R20.1 R23.2 R25.2 R27.2 R29.2 R30.2 R35.2 R36.1 R38.1 R39.1 R46.1 R53.1 R57.1 R58.1 R60.1 R62.1 R65.1 R71.1 R73.1 R76.1 R79.1 R80.1 R81.2 R82.1 R84.1 R85.2 R86.2 R89.2 R92.2 R94.2 R95.2 R96.2 R98.2 R99.2 R102.2 R104.2 R109.2 R112.2 R113.2 R114.2 R118.1 R119.1 R123.1 R124.1 R126.2 SB1.1 SB6.2 SB16.1 SB17.1 SB27.1 SB28.1 T4.2 T5.4 T5.8 T8.4 T8.8 T9.4 T9.8 T12.2 TP3.1 TP8.1 U1.3 U1.8 U2.3 U2.8 U3.3 U3.8 U4.3 U4.8 U5.3 U5.8 U6.39 U7.5 U8.B5 U8.D3 U8.F3 U8.F4 U8.H2 U9.3 U9.8 U10.2 U11.3 U11.8 U12.3 U12.8 U13.41 U14.2 U15.3 U15.8 U16.8 U16.9 U16.13 U16.18 U16.21 U17.8 U17.9 U17.13 U17.18 U17.21 U18.7 U18.9 U19.3 U19.8 U20.3 U20.8 U21.7 U21.9 U22.7 U22.9 U23.2 U24.2 U25.2 U26.2 U27.2 U28.2 U29.2 Z2.1
VBUS1: C16.2 CN7.A4 CN7.A9 CN7.B4 CN7.B9 CN11.1 D6.1 R64.2 R69.2 SB25.2 U23.5
VBUS2: C15.2 CN5.A4 CN5.A9 CN5.B4 CN5.B9 D1.1 R63.2 R70.2 TP10.1 U24.5
VDD: C17.1 C35.1 C47.2 C51.2 C75.1 C76.1 C77.1 C78.1 C79.1 C80.1 C81.1 C82.1 C83.1 C84.1 C85.1 C86.1 C87.1 C88.1 C89.1 C90.1 C91.1 C92.1 C93.1 C94.1 C95.1 C101.1 C102.1 CN8.18 CN9.18 R8.1 R9.2 R13.1 R17.1 R21.1 R22.1 R24.1 R28.1 R51.2 R87.1 R88.1 R90.1 R91.1 R93.1 R97.1 R100.1 R103.1 R105.1 R106.2 R107.2 R108.1 R112.1 R114.1 SB59.2 U6.3 U6.6 U6.7 U6.10 U6.13 U6.19 U6.22 U6.25 U6.26 U6.29 U6.32 U6.38 U8.B2 U8.E3 U8.E4 U8.H3 U13.1 U13.6 U13.20 U13.28 U16.10 U17.10
1_CC1: D11.2 SB4.2 SB21.2 SB56.2 T2.3 T12.3
1_CC2: D12.2 SB5.2 SB22.2 SB57.2 T3.3 T4.3
1_SBU1: R39.2 SB58.2 U13.27 U17.15
1_SBU2: R38.2 SB53.2 U13.26 U17.14
2_SBU1: SB41.2 U8.A5 U16.15
2_SBU2: SB42.2 U8.A6 U16.14
A0: R13.2 R85.1 U6.33
A1: R17.2 R89.1 U6.34
A2: R22.2 R92.1 U6.35
ADDR1: R104.1 R105.2 U8.H5
ADDR2: R86.1 R87.2 U8.D4
AUX_N_1: CN6.17 R12.2 R27.1 U9.1
AUX_N_2: C14.2 CN2.17 R31.1 U3.2
AUX_P_1: CN6.15 R11.2 R26.1 U9.2
AUX_P_2: C13.2 CN2.15 R30.1 U3.1
C1_CC1: C112.2 CN7.A5 D5.6 SB54.1 SB56.1 U17.4
C1_CC2: C113.2 CN7.B5 D5.4 SB55.1 SB57.1 U17.5
C1_D+: CN7.A6 CN7.B6 SB61.2 SB63.2 SB71.1
C1_D-: CN7.A7 CN7.B7 SB60.2 SB62.2 SB70.1
C1_RX1+: CN7.B11 U13.30 U19.4
C1_RX1-: CN7.B10 U13.31 U19.5
C1_RX2+: CN7.A11 U13.40 U20.2
C1_RX2-: CN7.A10 U13.39 U20.1
C1_SBU1: CN7.A8 D5.3 SB58.1 U17.1
C1_SBU2: CN7.B8 D5.1 SB53.1 U17.2
C1_TX1+: C43.2 CN7.A2 U19.1
C1_TX1-: C40.2 CN7.A3 U19.2
C1_TX2+: C26.2 CN7.B2 U20.5
C1_TX2-: C37.2 CN7.B3 U20.4
C2_CC1: C110.2 CN5.A5 D2.6 SB44.1 SB50.1 U16.4
C2_CC2: C111.2 CN5.B5 D2.4 SB45.1 SB49.1 U16.5
C2_D+: CN5.A6 CN5.B6 SB65.1 SB67.1 SB69.1
C2_D-: CN5.A7 CN5.B7 SB64.1 SB66.1 SB68.1
C2_RX1+: CN5.B11 U8.H6 U11.1
C2_RX1-: CN5.B10 U8.J6 U11.2
C2_RX2+: CN5.A11 U5.2 U8.D6
C2_RX2-: CN5.A10 U5.1 U8.E6
C2_SBU1: CN5.A8 D2.3 SB41.1 U16.1
C2_SBU2: CN5.B8 D2.1 SB42.1 U16.2
C2_TX1+: CN5.A2 U8.G6 U11.4
C2_TX1-: CN5.A3 U8.F6 U11.5
C2_TX2+: CN5.B2 U5.5 U8.C6
C2_TX2-: CN5.B3 U5.4 U8.B6
CON1_D+: CN10.1 SB61.1
CON1_D-: CN10.2 SB60.1
CON2_D+: CN10.3 SB67.2
CON2_D-: CN10.4 SB66.2
CS: R18.1 R88.2 U6.17
DCDC_EN: R3.1 R6.2 R82.2 SB23.2 SB26.1 U7.3
DISCHARGE_1: CN9.8 SB35.1
DISCHARGE_2: CN9.9 SB36.1
DP_PWR_SINK: CN6.20 SB43.2 TP4.1
DP_PWR_SOURCE: CN2.20 SB40.1 TP1.1
DPEQ0_A1: R98.1 R100.2 U13.14
DPEQ1: R16.1 R21.2 U13.2
EQ0: R97.2 R99.1 U13.38
EQ1: R102.1 R108.2 U13.35
FRS_TX1: CN8.8 R113.1 T12.1
FRS_TX2: CN8.9 R35.1 T4.1
GAIN: R24.2 R94.1 U6.36
HPD_SOURCE: CN2.18 CN9.7 R81.1 U3.4
HPDIN: CN6.18 CN8.11 R96.1 SB20.2 SB48.2 U9.4
I2C_EN_1: R103.2 R109.1 U13.17
I2C_EN_2: R23.1 R91.2 U6.16
I2C_SCL: CN9.3 R107.1 SB7.1 SB18.2 U8.J4
I2C_SDA: CN9.4 R106.1 SB10.1 SB19.2 U8.H4
ISENSE_1: CN9.11 U23.6
ISENSE_2: CN9.13 U24.6
L0_N_1: C24.1 CN6.10 U12.2
L0_N_2: C6.2 CN2.3 U1.2
L0_P_1: C23.1 CN6.12 U12.1
L0_P_2: C5.2 CN2.1 U1.1
L1_N_1: C36.1 CN6.7 U12.5
L1_N_2: C8.2 CN2.6 U1.5
L1_P_1: C25.1 CN6.9 U12.4
L1_P_2: C7.2 CN2.4 U1.4
L2_N_1: C42.1 CN6.4 U15.2
L2_N_2: C10.2 CN2.9 U2.2
L2_P_1: C39.1 CN6.6 U15.1
L2_P_2: C9.2 CN2.7 U2.1
L3_N_1: C46.1 CN6.1 U15.5
L3_N_2: C12.2 CN2.12 U2.5
L3_P_1: C44.1 CN6.3 U15.4
L3_P_2: C11.2 CN2.10 U2.4
LOCAL_PWR1: D3.1 R47.1 R49.1 R52.1 R56.1 R69.1 T6.5 T6.6 T6.7 T6.8 T10.5 T10.6 T10.7 T10.8 TP9.1 U23.4
LOCAL_PWR2: CN12.1 JP5.3 R48.1 R50.1 R55.1 R59.1 R70.1 U24.4
NETC1_1: C1.1 CN3.2 CN3.5 L1.1 Z1.2
NETC1_2: C1.2 CN3.1 CN3.3 L1.2 Z1.1
NETC3_1: C3.1 R64.1 R119.2 U28.3
NETC4_1: C4.1 R42.2 T6.1 T6.2 T6.3 T7.1 T7.2 T7.3
NETC4_2: C4.2 R41.2 R42.1 T6.4 T7.4
NETC5_1: C5.1 U6.31
NETC6_1: C6.1 U6.30
NETC7_1: C7.1 U6.28
NETC8_1: C8.1 U6.27
NETC9_1: C9.1 U6.24
NETC10_1: C10.1 U6.23
NETC11_1: C11.1 U6.21
NETC12_1: C12.1 U6.20
NETC13_1: C13.1 U8.A3
NETC14_1: C14.1 U8.A4
NETC18_1: C18.1 R63.1 R118.2 U27.3
NETC19_2: C19.2 U13.8
NETC20_2: C20.2 U13.7
NETC21_2: C21.2 U13.5
NETC22_2: C22.2 U13.4
NETC23_2: C23.2 U13.9
NETC24_2: C24.2 U13.10
NETC25_2: C25.2 U13.12
NETC26_1: C26.1 U13.37
NETC27_1: C27.1 U8.A1
NETC27_2: C27.2 U6.1
NETC28_1: C28.1 U8.A2
NETC28_2: C28.2 U6.2
NETC29_1: C29.1 U8.F1
NETC29_2: C29.2 U6.4
NETC30_1: C30.1 U8.G1
NETC30_2: C30.2 U6.5
NETC31_1: C31.1 U8.H1
NETC31_2: C31.2 U6.8
NETC32_1: C32.1 U8.J1
NETC32_2: C32.2 U6.9
NETC33_1: C33.1 U8.C1
NETC33_2: C33.2 U6.11
NETC34_1: C34.1 U8.B1
NETC34_2: C34.2 U6.12
NETC36_2: C36.2 U13.13
NETC37_1: C37.1 U13.36
NETC39_2: C39.2 U13.15
NETC40_1: C40.1 U13.34
NETC42_2: C42.2 U13.16
NETC43_1: C43.1 U13.33
NETC44_2: C44.2 U13.18
NETC46_2: C46.2 U13.19
NETC48_1: C48.1 R83.1 R84.2 U29.3
NETC49_1: C49.1 R40.2
NETC50_1: C50.1 R40.1 U18.6
NETC54_1: C54.1 U17.3
NETC55_1: C55.1 R117.2
NETC55_2: C55.2 C58.2 U21.4
NETC56_1: C56.1 R110.1
NETC56_2: C56.2 D4.2 L2.1 R111.2 U18.8
NETC57_1: C57.1 R54.1 R61.2
NETC58_1: C58.1 R32.1 R74.1 R117.1 R123.2 U21.5
NETC60_2: C60.2 R67.2
NETC61_1: C61.1 R65.2 R66.1 R67.1 R68.1 U22.5
NETC61_2: C61.2 C62.2 U22.4
NETC62_1: C62.1 R66.2
NETC72_1: C72.1 R77.1 R79.2 U25.3
NETC73_1: C73.1 R78.1 R80.2 U26.3
NETC74_2: C74.2 R74.2
NETC96_1: C96.1 U16.3
NETC108_1: C108.1 R111.1
NETC109_1: C109.1 R127.1
NETC109_2: C109.2 R45.1 SB3.1 SB13.1 U18.5
NETCN1_1: CN1.1 JP3.2
NETCN1_2: CN1.2 SB64.2
NETCN1_3: CN1.3 SB65.2
NETCN2_13: CN2.13 R4.1
NETCN2_14: CN2.14 R5.1
NETCN2_19: CN2.19 SB1.2
NETCN4_1: CN4.1 R1.1
NETCN4_2: CN4.2 SB62.1
NETCN4_3: CN4.3 SB63.1
NETCN6_13: CN6.13 R20.2
NETCN6_14: CN6.14 R15.2
NETCN6_19: CN6.19 SB6.1
NETCN8_17: CN8.17 SB59.1
NETCN9_15: CN9.15 SB24.2 U7.1
NETD3_2: D3.2 D8.2 JP5.1 T10.1 T10.2 T10.3
NETD7_2: D7.2 L4.1 U21.1
NETD9_2: D9.2 L5.1 U22.1
NETD11_1: D11.1 U10.1
NETD12_1: D12.1 U14.1
NETLD1_1: LD1.1 R125.1
NETLD2_1: LD2.1 R10.1
NETR7_1: R7.1 R53.2 R54.2
NETR7_2: R7.2 SB3.2
NETR11_1: R11.1 R36.2 U13.24
NETR12_1: R12.1 R37.2 U13.25
NETR14_1: R14.1 U6.18
NETR32_2: R32.2 R75.1
NETR33_2: R33.2 R34.2 SB8.2 SB9.2 U10.5 U14.5
NETR41_1: R41.1 T5.1 T5.2 T5.5 T5.6 T5.7
NETR43_2: R43.2 SB13.2
NETR47_2: R47.2 R49.2 R52.2 R56.2 T8.1 T8.2 T8.5 T8.6 T8.7
NETR48_2: R48.2 R50.2 R55.2 R59.2 T9.1 T9.2 T9.5 T9.6 T9.7
NETR57_2: R57.2 SB35.2 T8.3
NETR58_2: R58.2 SB36.2 T9.3
NETR62_2: R62.2 U18.4
NETR71_2: R71.2 U22.6
NETR72_2: R72.2 T10.4
NETR76_2: R76.2 U21.6
NETR101_2: R101.2 U29.4
NETR110_2: R110.2 U18.1
NETR115_2: R115.2 U27.4
NETR116_2: R116.2 U28.4
NETR120_1: R120.1 SB24.1 U7.6
NETR121_1: R121.1 U24.1 U26.1
NETR121_2: R121.2 U26.4
NETR122_1: R122.1 U23.1 U25.1
NETR122_2: R122.2 U25.4
NETR126_1: R126.1 SB25.1
NETSB7_2: SB7.2 U6.15
NETSB10_2: SB10.2 U6.14
NETSB11_2: SB11.2 T3.1
NETSB12_2: SB12.2 T2.1
NETSB16_2: SB16.2 SB50.2 U16.7
NETSB17_2: SB17.2 SB49.2 U16.6
NETSB18_1: SB18.1 U13.21
NETSB19_1: SB19.1 U13.22
NETSB20_1: SB20.1 U13.23
NETSB21_1: SB21.1 U17.12
NETSB22_1: SB22.1 U17.11
NETSB26_2: SB26.2 U18.3
NETSB27_2: SB27.2 SB55.2 U17.6
NETSB28_2: SB28.2 SB54.2 U17.7
NETSB33_2: SB33.2 U21.3
NETSB37_2: SB37.2 U22.3
NETSB48_1: SB48.1 U13.32
NETSB51_1: SB51.1 U16.11
NETSB52_1: SB52.1 U16.12
NETSB68_2: SB68.2 U16.20
NETSB69_2: SB69.2 U16.19
NETSB70_2: SB70.2 U17.20
NETSB71_2: SB71.2 U17.19
NETTP6_1: TP6.1 U13.29
PORT1_CC1: CN8.1 D10.1 JP2.1 SB4.1 T2.2
PORT1_CC2: CN8.2 D10.3 JP1.1 SB5.1 T3.2
PORT1_DB1: CN8.3 JP2.2
PORT1_DB2: CN8.4 JP1.2
PORT2_CC1: CN8.13 D10.4 SB44.2 SB52.2
PORT2_CC2: CN8.14 D10.6 SB45.2 SB51.2
PSU: C2.1 C59.1 C65.1 C71.1 C105.1 C106.1 C107.1 D8.1 L1.3 R3.2 R72.1 R73.2 R125.2 SB33.1 TP2.1 U18.2 U21.8
PWD#: CN9.6 R25.1 U6.37
PWM_CTL: R51.1 R61.1 SB2.2
SOURCE_EN: CN8.15 R124.2 T5.3
SSEQ0_A0: R93.2 R95.1 U13.11
SSEQ1: R19.1 R90.2 U13.3
SSRX+: C21.1 CN4.6 U4.4
SSRX-: C22.1 CN4.5 U4.5
SSTX+: C19.1 CN4.9 U4.1
SSTX-: C20.1 CN4.8 U4.2
SW_EN: R28.2 R29.1 U8.J5
USB3_DET: CN9.2 R1.2 R2.1
V_CTL1: CN8.12 SB2.1 SB14.1
V_CTL2: CN9.1 SB15.1 SB23.1
VCONN_EN1: CN8.6 R9.1 R33.1 SB12.1 U10.4
VCONN_EN2: CN8.7 R8.2 R34.1 SB11.1 U14.4
VCONN_OUT: C45.1 C74.1 JP3.1 L4.2 R75.2 SB9.1 TP5.1
VDC: C66.1 C67.1 JP5.2 SB37.1 U22.8
VSENSE_1: CN9.10 R116.1 U28.1
VSENSE_2: CN9.12 R115.1 U27.1
VSENSE_DCDC: R101.1 U7.4 U29.1
VSOURCE: C52.1 C53.1 C103.1 C104.1 L2.2 R45.2 R60.2 R83.2 R127.2 T7.5 T7.6 T7.7 T7.8
VSOURCE_9V: R44.1 R46.2 SB14.2
VSOURCE_15V: R43.1 R44.2 SB15.2

Pads without a net: CN3 4 6 7 8 9; CN5 5 6; CN7 5 6; CN9 16 17; U1 6 7 9 10; U2 6 7 9 10; U3 5 6 7 9 10; U4 6 7 9 10; U5 6 7 9 10; U8 B3 B4 D1 E1 J2 J3; U9 5 6 7 9 10; U10 3; U11 6 7 9 10; U12 6 7 9 10; U14 3; U15 6 7 9 10; U16 16 17; U17 16 17; U19 6 7 9 10; U20 6 7 9 10; U21 2; U22 2

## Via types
v1: diameter 0.61, hole 0.305, TOP to BOTTOM, 420 vias
v2: diameter 0.508, hole 0.254, TOP to BOTTOM, 174 vias
v3: diameter 0.406, hole 0.203, TOP to BOTTOM, 12 vias

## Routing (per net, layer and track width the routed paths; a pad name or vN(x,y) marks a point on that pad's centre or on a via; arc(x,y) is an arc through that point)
+3V3: length 181.3
  TOP w0.356: U24.3 46.32,9.37 C69.1 ; U23.3 24.23,3.53 C68.1
  TOP w0.381: C63.1 19.37,17.59 U25.5
  TOP w0.508: C63.1 19.56,18.67 19.94,19.05 v1(20.83,19.05) ; U26.5 40.83,25.33 C64.1 v1(39.88,25.4) ; v1(14.22,31.11) 17.27,31.11 22.1,26.29 v1(22.61,26.29) 24.38,28.07 26.16,28.07 27.43,29.34 R37.1 ; v1(71.37,62.61) 76.58,57.4 76.58,51.94 v1(73.79,49.15) ; C68.1 v1(23.37,4.45) ; v1(49.66,49.15) 49.28,48.77 C41.1 49.09,47.69 U29.5 ; C69.1 v1(47.5,9.4)
  L3_SIG w0.508: CN9.14 37.21,14.99 ; CN9.14 35.43,14.99 ; CN9.14 36.32,14.1 ; CN9.14 36.32,15.88 ; v2(21.34,45.34) 21.21,45.47 21.21,48.01 20.7,48.51 18.92,48.51 18.41,48.01 18.41,46.48 17.65,45.72 15.49,45.72 v1(14.61,44.83)
  BOTTOM w0.178: C38.1 45.59,12.7 U7.2
  BOTTOM w0.508: SB40.2 71.5,62.48 v1(71.37,62.61) 70.87,63.12 69.85,63.12 69.22,62.48 R31.2 ; v1(14.22,31.11) 12.95,32.38 10.67,32.38 9.53,33.53 9.53,42.29 10.54,43.31 SB43.1 14.1,44.32 v1(14.61,44.83) ; C99.1 28.45,25.65 27.81,26.29 v1(22.61,26.29) ; C99.1 28.51,24.83 U28.5 ; C99.1 32.13,24.89 33.66,26.42 37.85,26.42 39.24,25.02 v1(39.24,24.89) ; U27.5 54.16,26.71 54.1,26.77 C98.1 v1(54.1,28.57) 47.37,35.31 47.37,46.86 v1(49.66,49.15) v1(73.79,49.15) ; CN9.14 C100.1 39.5,14.35 v1(38.99,13.84) ; v2(21.34,45.34) 21.46,45.34 R26.2 ; C38.1 v1(44.32,13.08) ; v1(20.57,15.11) 19.81,14.35 R77.2 ; R120.2 39.88,11.43 v1(39.24,12.06) ; R78.2 v1(40.01,21.34)
+5V: length 42.8
  BOTTOM w0.508: JP3.3 80.14,53.98 83.82,50.29 85.98,50.29 92.33,43.94 92.33,40.64 94.49,38.48 94.49,34.04 95.63,32.89 95.63,25.27 C97.1 98.17,25.02 CN8.10
D5V: length 96.5
  TOP w0.508: 94.61,10.6 R10.2 ; R10.2 94.03,11.18 ; R10.2 95.2,11.18 ; 92.08,10.38 Z2.2 ; Z2.2 91.06,11.56 ; Z2.2 93.09,11.56 ; 95.89,11.3 95.89,24.33 95.3,24.92 92.99,24.92 92.25,25.65 85.98,25.65 84.33,27.3 84.33,32.26 85.85,33.78 SB8.1 ; TP7.1 94.61,9.2 ; TP7.1 95.56,8.26 ; TP7.1 94.61,7.31 ; TP7.1 93.67,8.26 ; L5.2 87.13,10.05 ; L5.2 84.95,7.11 ; L5.2 89.3,7.11 ; L5.2 87.13,4.18 ; 97.41,9.91 CN8.16 ; CN8.16 98.3,10.8 ; CN8.16 98.3,9.02 ; CN8.16 99.19,9.91 ; C70.1 91.19,6.68 ; C70.1 89.74,5.92 ; C70.1 91.19,5.16 ; C70.1 92.63,5.92 ; v1(60.83,10.92) C60.1 R68.2
  BOTTOM w0.508: v1(60.83,10.92) 81.28,10.92 84.96,7.24 v1(90.42,7.24)
GND: length 470.1
  TOP w0.203: U17.18 v2(15.88,23.37) ; U17.13 15.88,25.65 v1(15.75,25.78) ; U16.18 v2(99.06,54.99) U16.13 ; U16.8 96.75,54.99 v1(96.57,54.81) 96.79,54.59 U16.9 ; U17.9 17.96,23.77 v2(18.16,23.57) 17.96,23.37 U17.8
  TOP w0.254: CN2.11 66.04,60.45 v1(66.04,62.28) ; CN5.A12 104.92,44.74 CN5.B1 ; U11.3 U11.8 100.61,39.24 v1(99.85,38.48) ; v3(82.7,43.26) 82.92,43.47 U8.B5 ; v1(11.38,40.6) 13.21,40.6 CN6.16 ; CN6.2 13.21,33.6 v1(11.38,33.6) ; CN6.11 13.21,38.1 v1(11.38,38.1) ; CN2.5 63.04,60.45 v1(63.04,62.28) ; U4.3 U4.8 v1(15.62,54.86) ; v1(64.54,62.28) 64.54,60.45 CN2.8 ; U5.3 U5.8 100.65,44.74 100.43,44.96 100.43,45.02 100.43,45.02 100.43,45.77 100.07,46.13 v1(100.07,46.2) ; U8.F3 81.57,41.66 81.33,41.43 v3(81.33,41.43) 81.33,40.75 U8.H2 ; CN7.B1 9.38,13.68 CN7.A12 ; CN7.A1 9.38,19.18 CN7.B12 ; CN2.2 61.54,60.45 v1(61.54,62.28) ; v1(11.38,35.1) 11.38,35.1 CN6.5 ; CN5.B12 104.92,39.24 CN5.A1 ; U19.3 U19.8 14.71,19.08 15,18.78 v1(15,18.41) ; CN2.16 68.54,62.66 69,63.12 69.72,63.12 v1(70.61,62.23) ; U8.D3 81.92,43.06 v3(82.04,43.18) ; v1(11.38,36.6) 11.38,36.6 CN6.8 ; U8.F4 v3(82.88,41.66)
  TOP w0.356: T9.8 T9.4 v1(41.9,26.65) ; v1(44.45,8.26) 44.32,8.38 U24.2
  TOP w0.381: v1(71.12,54.74) 70.99,54.86 U3.3 U3.8 ; U9.3 U9.8 18.9,40.39 v1(18.97,40.31) ; v1(45.15,37.78) 45.45,37.48 T5.4 T5.8 ; v1(62.23,54.74) U1.3 U1.8 ; U20.3 U20.8 v1(15.01,12.34) ; v1(18.95,34.54) 18.69,34.29 U15.8 U15.3 ; U12.3 U12.8 18.75,37.34 v1(19,37.08) ; U23.2 v1(22.1,2.54) ; U2.8 U2.3 v1(65.28,54.74)
  TOP w0.508: v1(17.65,15.75) 17.4,15.49 16.06,15.49 D5.5 D5.2 ; C2.2 43.56,55.42 ; C2.2 43.56,52.02 ; C2.2 40.84,53.72 ; 65.28,17.35 C52.2 ; C52.2 66.03,18.16 ; C52.2 65.28,18.97 ; R2.2 v1(25.15,59.03) ; 75.83,16.13 C106.2 ; C106.2 76.45,16.71 ; C106.2 76.45,15.54 ; R36.1 v1(26.16,29.13) ; 104.9,9.65 U21.7 104.9,7.49 105.41,6.99 105.41,4.83 104.9,4.32 R76.1 104.52,1.4 105.03,0.89 108.97,0.89 109.73,1.65 ; R65.1 v1(61.34,14.86) ; v1(94.74,28.32) R35.2 92.35,28.32 T4.2 ; C53.2 68.57,22.73 ; C53.2 66.84,21.82 ; C53.2 65.11,22.73 ; C53.2 66.84,23.65 ; C51.1 19.81,26.29 v1(19.94,26.42) ; D7.1 112.07,8.64 ; D7.1 108.41,8.64 ; D7.1 110.24,7.32 ; D7.1 110.24,9.96 ; C108.2 v1(77.98,34.04) ; D10.2 v1(91.31,42.55) ; C63.2 v1(22.23,17.78) ; C107.2 76.45,18.11 ; C107.2 75.83,17.53 ; C107.2 76.45,16.94 ; R58.1 v1(40.51,26.8) ; v1(48.51,40.51) 48.9,40.13 R84.1 ; R23.2 R18.2 72.77,44.32 v1(73.41,44.96) ; R38.1 v1(28.7,29.15) ; U29.2 v1(50.04,42.8) ; R29.2 v1(84.58,33.78) ; 78.49,26.8 U18.7 C50.2 C49.2 ; v1(17.5,18.29) 17.14,18.29 16.89,18.54 C54.2 ; R126.2 v1(13.18,7.24) ; 63.83,4.19 D9.1 ; D9.1 65.15,2.36 ; D9.1 66.47,4.19 ; D9.1 65.15,6.02 ; C57.2 91.14,20.65 v1(91.14,21.18) ; v1(74.42,36.58) 74.42,37.85 74.04,38.23 73.66,37.85 v1(73.66,36.58) ; C69.2 v1(47.5,10.92) ; R39.1 v1(29.97,29.15) ; R57.1 32.58,19.3 ; R57.1 32,18.72 ; R57.1 32,19.89 ; U14.2 v1(89.15,31.24) ; R5.2 v1(68.71,53.98) ; LD1.2 38.99,56.39 ; R25.2 v1(56.13,40.51) ; v1(43.31,26.16) 42.55,25.4 C64.2 ; 102.59,34.14 C45.2 ; C45.2 104.12,34.14 ; C45.2 103.35,35.59 ; C45.2 103.35,32.69 ; C105.2 76.33,20.12 ; C105.2 75.58,19.3 ; C105.2 76.33,18.49 ; v1(93.6,14.99) 94.36,15.75 LD2.2 ; SB16.1 v1(92.96,55.75) ; 58.37,4.24 C66.2 ; C66.2 61.27,4.24 ; C66.2 59.82,5 ; C66.2 59.82,3.48 ; R14.2 72.77,45.97 v1(73.41,45.97) ; v1(19.68,11.56) 19.68,12.45 C72.2 20.32,13.08 U25.2 ; R20.1 v1(22.99,43.43) ; C47.1 v1(93.22,54.74) ; 76.58,20.37 C59.2 75.96,20.95 ; 91.19,2.21 C70.2 ; C70.2 92.63,2.97 ; C70.2 89.74,2.97 ; C70.2 91.19,3.73 ; C65.2 109.84,5.97 ; C65.2 109.22,6.55 ; C65.2 109.22,5.38 ; 109.8,3.43 C71.2 ; C71.2 110.57,1.98 ; C71.2 111.33,3.43 ; C71.2 110.57,4.88 ; C68.2 v1(24.26,5.96) ; D4.1 73.03,23.67 ; D4.1 73.03,21.03 ; D4.1 71.2,22.35 ; D4.1 74.85,22.35 ; v1(18.41,42.16) 18.16,42.42 SB6.2 ; C17.2 v1(56.01,47.12) ; 68.07,9.53 U22.7 64.26,9.53 R71.1 62.99,9.14 62.61,9.53 56.77,9.53 55.75,8.51 55.75,5.84 56.9,4.7 57.53,4.7 ; R19.2 v1(29.08,45.85) ; R46.1 v1(91.06,21.97) ; 62.23,4.2 C67.2 ; C67.2 62.81,4.83 ; C67.2 61.65,4.83 ; C73.2 v1(40.01,19.81) ; D10.5 v1(91.31,47.88) ; R62.1 v1(83.95,21.97) ; C41.2 v1(51.94,47.88) ; R6.1 v1(83.31,18.41) ; R15.1 v1(22.99,44.7) ; SB17.1 92.96,57.4 v1(92.84,57.53) ; v1(20.95,24.64) SB28.1 ; R16.2 v1(32,45.62) ; U26.2 v1(41.78,22.48) ; R124.1 v1(50.55,36.32) ; SB1.1 v1(74.22,54.99) ; v1(90.68,14.86) 91.57,14.86 Z2.1 91.56,15.88 v1(90.68,15.88) ; C48.2 v1(51.05,38.48) ; R53.1 v1(85.09,20.19) ; R4.2 v1(67.44,53.98) ; SB27.1 v1(22.35,21.72)
  L3_SIG w0.508: 97.13,62.57 CN1.4 ; CN1.4 97.97,63.41 ; CN1.4 98.81,62.57 ; CN1.4 97.97,61.73 ; 14.5,59.82 CN4.4 ; CN4.4 14.5,61.5 ; CN4.4 15.34,60.66 ; CN4.4 13.66,60.66 ; 58.3,68.2 CN2.23 ; CN2.23 57.26,69.74 ; CN2.23 59.34,69.74 ; CN2.23 58.3,71.28 ; 10.16,1.98 TP8.1 ; TP8.1 9.22,2.92 ; TP8.1 11.1,2.92 ; TP8.1 10.16,3.86 ; CN6.21 10.7,31.4 ; CN6.21 8.91,30.36 ; CN6.21 12.49,30.36 ; CN6.21 10.7,29.32 ; CN6.22 12.49,46.86 ; CN6.22 10.7,47.9 ; CN6.22 10.7,45.82 ; CN6.22 8.91,46.86 ; TP3.1 89.66,57.96 ; TP3.1 90.6,57.02 ; TP3.1 88.72,57.02 ; TP3.1 89.66,56.08 ; 3.92,45.82 CN6.24 ; CN6.24 2.38,46.86 ; CN6.24 3.92,47.9 ; CN6.24 5.46,46.86 ; 21.6,61.57 CN4.10 ; CN4.10 22.8,63.36 ; CN4.10 21.6,65.15 ; CN4.10 20.41,63.36 ; 2.38,30.36 CN6.23 ; CN6.23 3.92,29.32 ; CN6.23 3.92,31.4 ; CN6.23 5.46,30.36 ; 57.26,62.96 CN2.21 ; CN2.21 59.34,62.96 ; CN2.21 58.3,61.17 ; CN2.21 58.3,64.75 ; CN4.7 15.75,57.41 ; CN4.7 15.75,55.91 ; CN4.7 15,56.66 ; CN4.7 16.5,56.66 ; L1.4 50.19,65.66 ; L1.4 49.02,66.83 ; L1.4 47.85,65.66 ; L1.4 49.02,64.49 ; 80.14,61.34 81.08,61.34 ; 80.14,61.34 80.14,60.4 ; 80.14,61.34 80.14,62.28 ; 80.14,61.34 79.2,61.34 ; L1.6 46.52,64.33 ; L1.6 45.35,63.16 ; L1.6 46.52,61.99 ; L1.6 47.69,63.16 ; L1.5 55.19,65.66 ; L1.5 54.02,64.49 ; L1.5 52.85,65.66 ; L1.5 54.02,66.83 ; 94.9,63.7 CN1.5 ; CN1.5 93.33,65.28 ; CN1.5 96.48,65.28 ; CN1.5 94.9,66.85 ; CN4.11 11.1,63.36 ; CN4.11 9.9,65.15 ; CN4.11 8.71,63.36 ; CN4.11 9.9,61.57 ; CN12.2 32.26,5.3 ; CN12.2 31.28,4.32 ; CN12.2 33.24,4.32 ; CN12.2 32.26,3.34 ; CN2.22 74.8,64.75 ; CN2.22 74.8,61.17 ; CN2.22 75.84,62.96 ; CN2.22 73.76,62.96 ; 87.88,61.34 87.88,62.28 ; 87.88,61.34 88.82,61.34 ; 87.88,61.34 87.88,60.4 ; 87.88,61.34 86.94,61.34 ; 73.76,69.74 CN2.24 ; CN2.24 74.8,68.2 ; CN2.24 74.8,71.28 ; 108.04,63.7 CN1.6 ; CN1.6 108.04,66.85 ; CN1.6 109.62,65.28 ; CN1.6 106.47,65.28 ; CN11.2 16.47,4.32 ; CN11.2 15.49,5.3 ; CN11.2 14.52,4.32 ; CN11.2 15.49,3.34
  BOTTOM w0.203: U7.5 v1(45.59,8.64)
  BOTTOM w0.381: v1(82.93,45.34) 82.93,44.2 C80.2 ; v1(80.29,44.32) 80.14,44.17 C81.2 ; v1(83.46,39.37) 83.69,39.6 C87.2
  BOTTOM w0.508: C98.2 v1(51.44,27.56) ; R30.2 v1(67.82,62.23) ; R82.1 C38.2 v1(45.21,15.75) ; 65,22.1 R60.1 ; R60.1 66.37,22.1 ; R60.1 65.68,20.65 ; R60.1 65.68,23.55 ; v1(10.41,12.45) 10.79,12.83 C16.1 ; v1(96.52,1.65) 96.01,1.65 C102.2 95.82,2.48 v1(96.58,2.48) ; 64.9,19.48 64.9,19.94 ; 64.9,19.94 65.35,19.94 ; 64.9,19.94 64.9,20.4 ; C101.2 v1(40.77,5.84) ; v1(19.56,34.92) 19.94,34.92 R109.2 ; R89.2 R85.2 57.02,45.72 v1(56.01,45.72) ; v2(27.3,39.24) 26.67,39.88 C90.2 ; C100.2 41.02,15.75 40.51,16.26 v1(38.99,16.26) ; v1(99.85,38.48) 100.2,38.48 C110.1 ; C96.2 97.79,56.26 v2(98.45,55.6) ; v1(21.46,25.65) 22.23,24.89 C99.2 ; C85.2 62.61,42.42 v2(62.36,42.67) ; v1(20.45,11.56) 20.45,11.94 C72.2 ; C15.1 v1(109.73,43.05) ; C51.1 19.81,26.29 v1(19.94,26.42) ; C83.2 67.44,42.42 v2(67.18,42.67) ; R25.2 v1(56.13,40.51) ; C91.2 v2(25.27,38.48) ; v1(103.96,49.15) 103.2,48.39 102.06,48.39 101.73,48.06 D2.5 ; D6.2 v1(2.67,14.61) ; C78.2 62.48,43.94 v2(62.36,44.07) ; v1(73.41,43.18) 73.41,42.67 72.52,41.78 C82.2 ; v1(73.41,45.97) 72.77,45.97 R14.2 ; C93.2 26.42,35.05 v2(26.29,35.18) ; v1(94.61,25.91) 94.61,26.04 R113.2 93.67,26.61 T12.2 ; v1(70.61,62.23) R81.2 ; v1(14.99,20.7) C112.1 ; C111.1 108.33,42.14 108.92,42.72 v1(108.92,42.88) ; C86.2 60.83,42.29 v1(60.33,41.78) ; C89.2 80.14,40.01 v1(81.01,39.13) ; R118.1 v1(53.72,20.57) C18.2 53.21,22.1 U27.2 ; R29.2 v1(84.58,33.78) ; D1.2 v1(111.25,43.05) ; R86.2 v1(77.22,43.18) ; v1(75.95,42.16) 75.95,41.15 C92.2 76.83,41.02 v1(76.83,42.16) ; U14.2 v1(89.15,31.24) ; C113.1 17.53,21.59 18.03,21.08 v1(18.29,21.08) ; R102.2 R99.2 32.64,38.1 33.08,37.66 33.8,37.66 33.99,37.85 v1(34,37.85) ; v2(67.18,44.2) 67.44,43.94 C76.2 ; v1(18.64,30.86) 19.25,30.25 20.35,30.25 C95.2 20.07,31.5 v1(19.18,31.5) ; v2(23.04,47.73) 22.58,47.73 R27.2 ; R123.1 v1(100.84,4.32) ; R92.2 R94.2 v1(56.13,41.78) ; v2(64.77,42.67) 65.02,42.42 C84.2 ; v2(64.77,44.07) 64.9,43.94 C77.2 ; C97.2 93.22,25.65 v1(93.22,25.91) ; v1(59.82,44.2) 61.09,44.2 C79.2 ; 64.9,18.34 64.9,18.8 ; 64.9,18.8 64.9,19.25 ; 64.9,18.8 65.35,18.8 ; U28.2 27.56,19.43 R119.1 28.57,18.41 v1(29.92,18.41) ; C3.2 v1(23.37,21.72) ; v1(11.38,40.6) 11.6,40.39 R96.2 ; 24.77,13.08 v1(23.37,13.08) ; C94.2 19.94,32.38 v1(19.56,32.38) ; C73.2 v1(41.15,18.8) ; D2.2 v1(101.73,51.44) ; C47.1 v1(93.22,54.74) ; R98.2 20.37,39.37 19.74,40 v1(19.73,40) 20.38,40.64 R95.2
  vias: v1(1.27,24.51) v1(4.95,26.42) v1(6.83,22.76) v1(31.24,42.16) v1(31.24,40.26) v1(31.36,34.58) v1(31.36,32.35) v1(32.98,35.08) v1(33.02,20.32) v1(33.02,19.56) v1(34,39.62) v1(39.62,54.86) v1(39.62,53.98) v1(39.62,53.09) v1(40.39,54.86) v1(40.39,53.98) v1(40.39,53.09) v1(40.89,37.97) v1(43.43,37.97) v1(57.02,4.32) v1(57.02,3.43) v1(57.78,4.32) v1(57.78,3.43) v1(61.72,3.56) v1(62.74,3.56) v1(67.06,18.54) v1(67.06,17.65) v1(67.82,18.54) v1(67.82,17.65) v1(68.71,18.54) v1(68.71,17.65) v1(90.42,1.78) v1(90.42,1.02) v1(91.31,1.78) v1(91.31,1.02) v1(92.08,1.78) v1(92.08,1.02) v1(101.51,34.06) v1(101.5,33.27) v1(101.51,32.49) v1(102.26,34.06) v1(102.26,33.27) v1(102.26,32.49) v1(105.38,56.87) v1(106.4,58.8) v1(111.89,4.19) v1(111.89,3.3) v1(111.89,2.41) v1(112.78,4.19) v1(112.78,3.3) v1(112.78,2.41) v2(15.24,24) v2(15.24,22.73) v2(16.46,42.24) v2(16.51,24) v2(16.51,22.73) v2(19.51,47.73) v2(19.51,45.49) v2(19.51,42.39) v2(23.04,45.49) v2(25.27,37.21) v2(25.27,35.18) v2(26.29,39.24) v2(26.29,37.21) v2(27.3,37.21) v2(27.3,35.18) v2(60.43,35.83) v2(61.24,35.83) v2(62.36,45.47) v2(62.97,35.83) v2(63.78,35.83) v2(64.77,45.47) v2(65.51,35.83) v2(66.32,35.83) v2(67.18,45.47) v2(68.05,35.83) v2(68.86,35.83) v2(77.72,27.05) v2(77.72,25.27) v2(77.78,40.68) v2(77.78,38.44) v2(78.29,44.05) v2(78.29,43.34) v2(78.97,42.53) v2(78.97,40.3) v2(79.12,26.16) v2(80.52,27.05) v2(80.52,25.27) v2(80.81,46.86) v2(81.52,46.86) v2(86.47,43.57) v2(86.47,42.15) v2(86.49,40.76) v2(86.96,39.79) v2(86.96,39.08) v2(87.91,42.13) v2(88.58,45.09) v2(88.58,44.32) v2(98.45,54.38) v2(99.67,55.6) v2(99.67,54.38)
